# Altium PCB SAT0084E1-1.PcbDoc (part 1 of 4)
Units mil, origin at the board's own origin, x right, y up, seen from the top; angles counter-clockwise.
Board outline 7055 x 5555 mil, 6 copper layers (Top Layer, MidLayer1-GND, MidLayer2-HiSp, MidLayer3-GND, MidLayer4, Bottom Layer), stack 57.4 mil thick; 379 components, 207 nets, 1026 pads, 1546 vias.
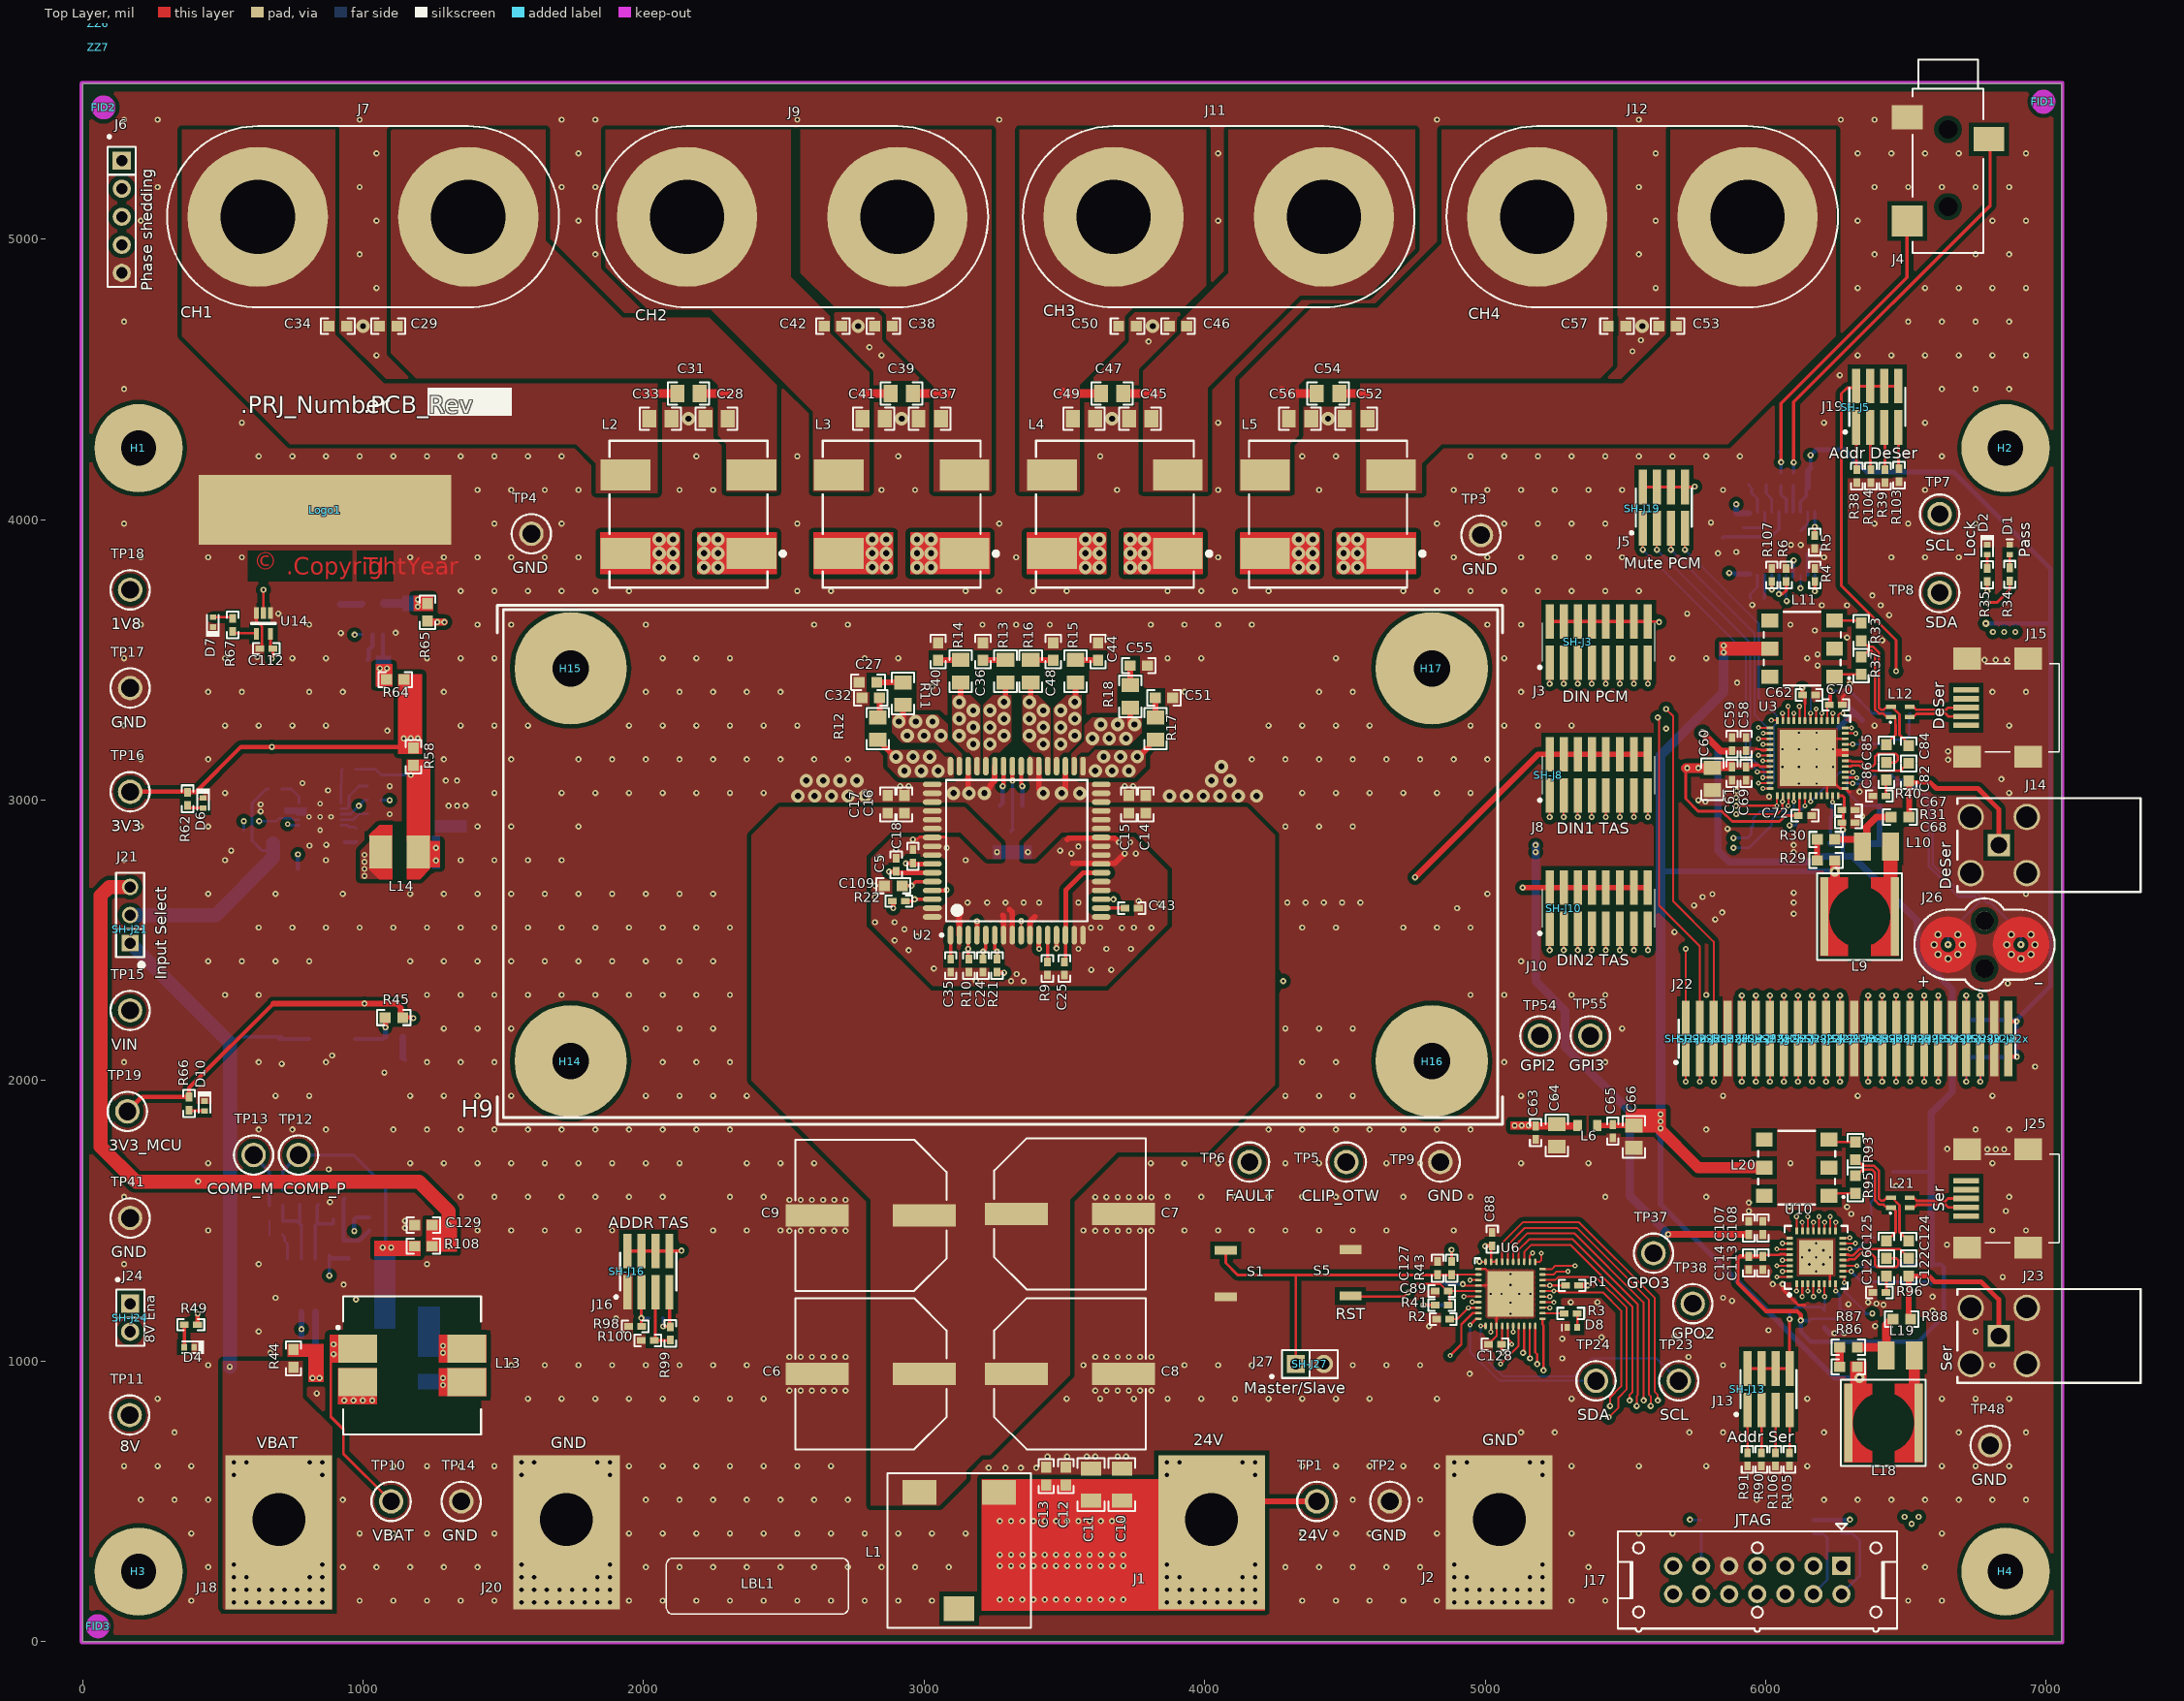
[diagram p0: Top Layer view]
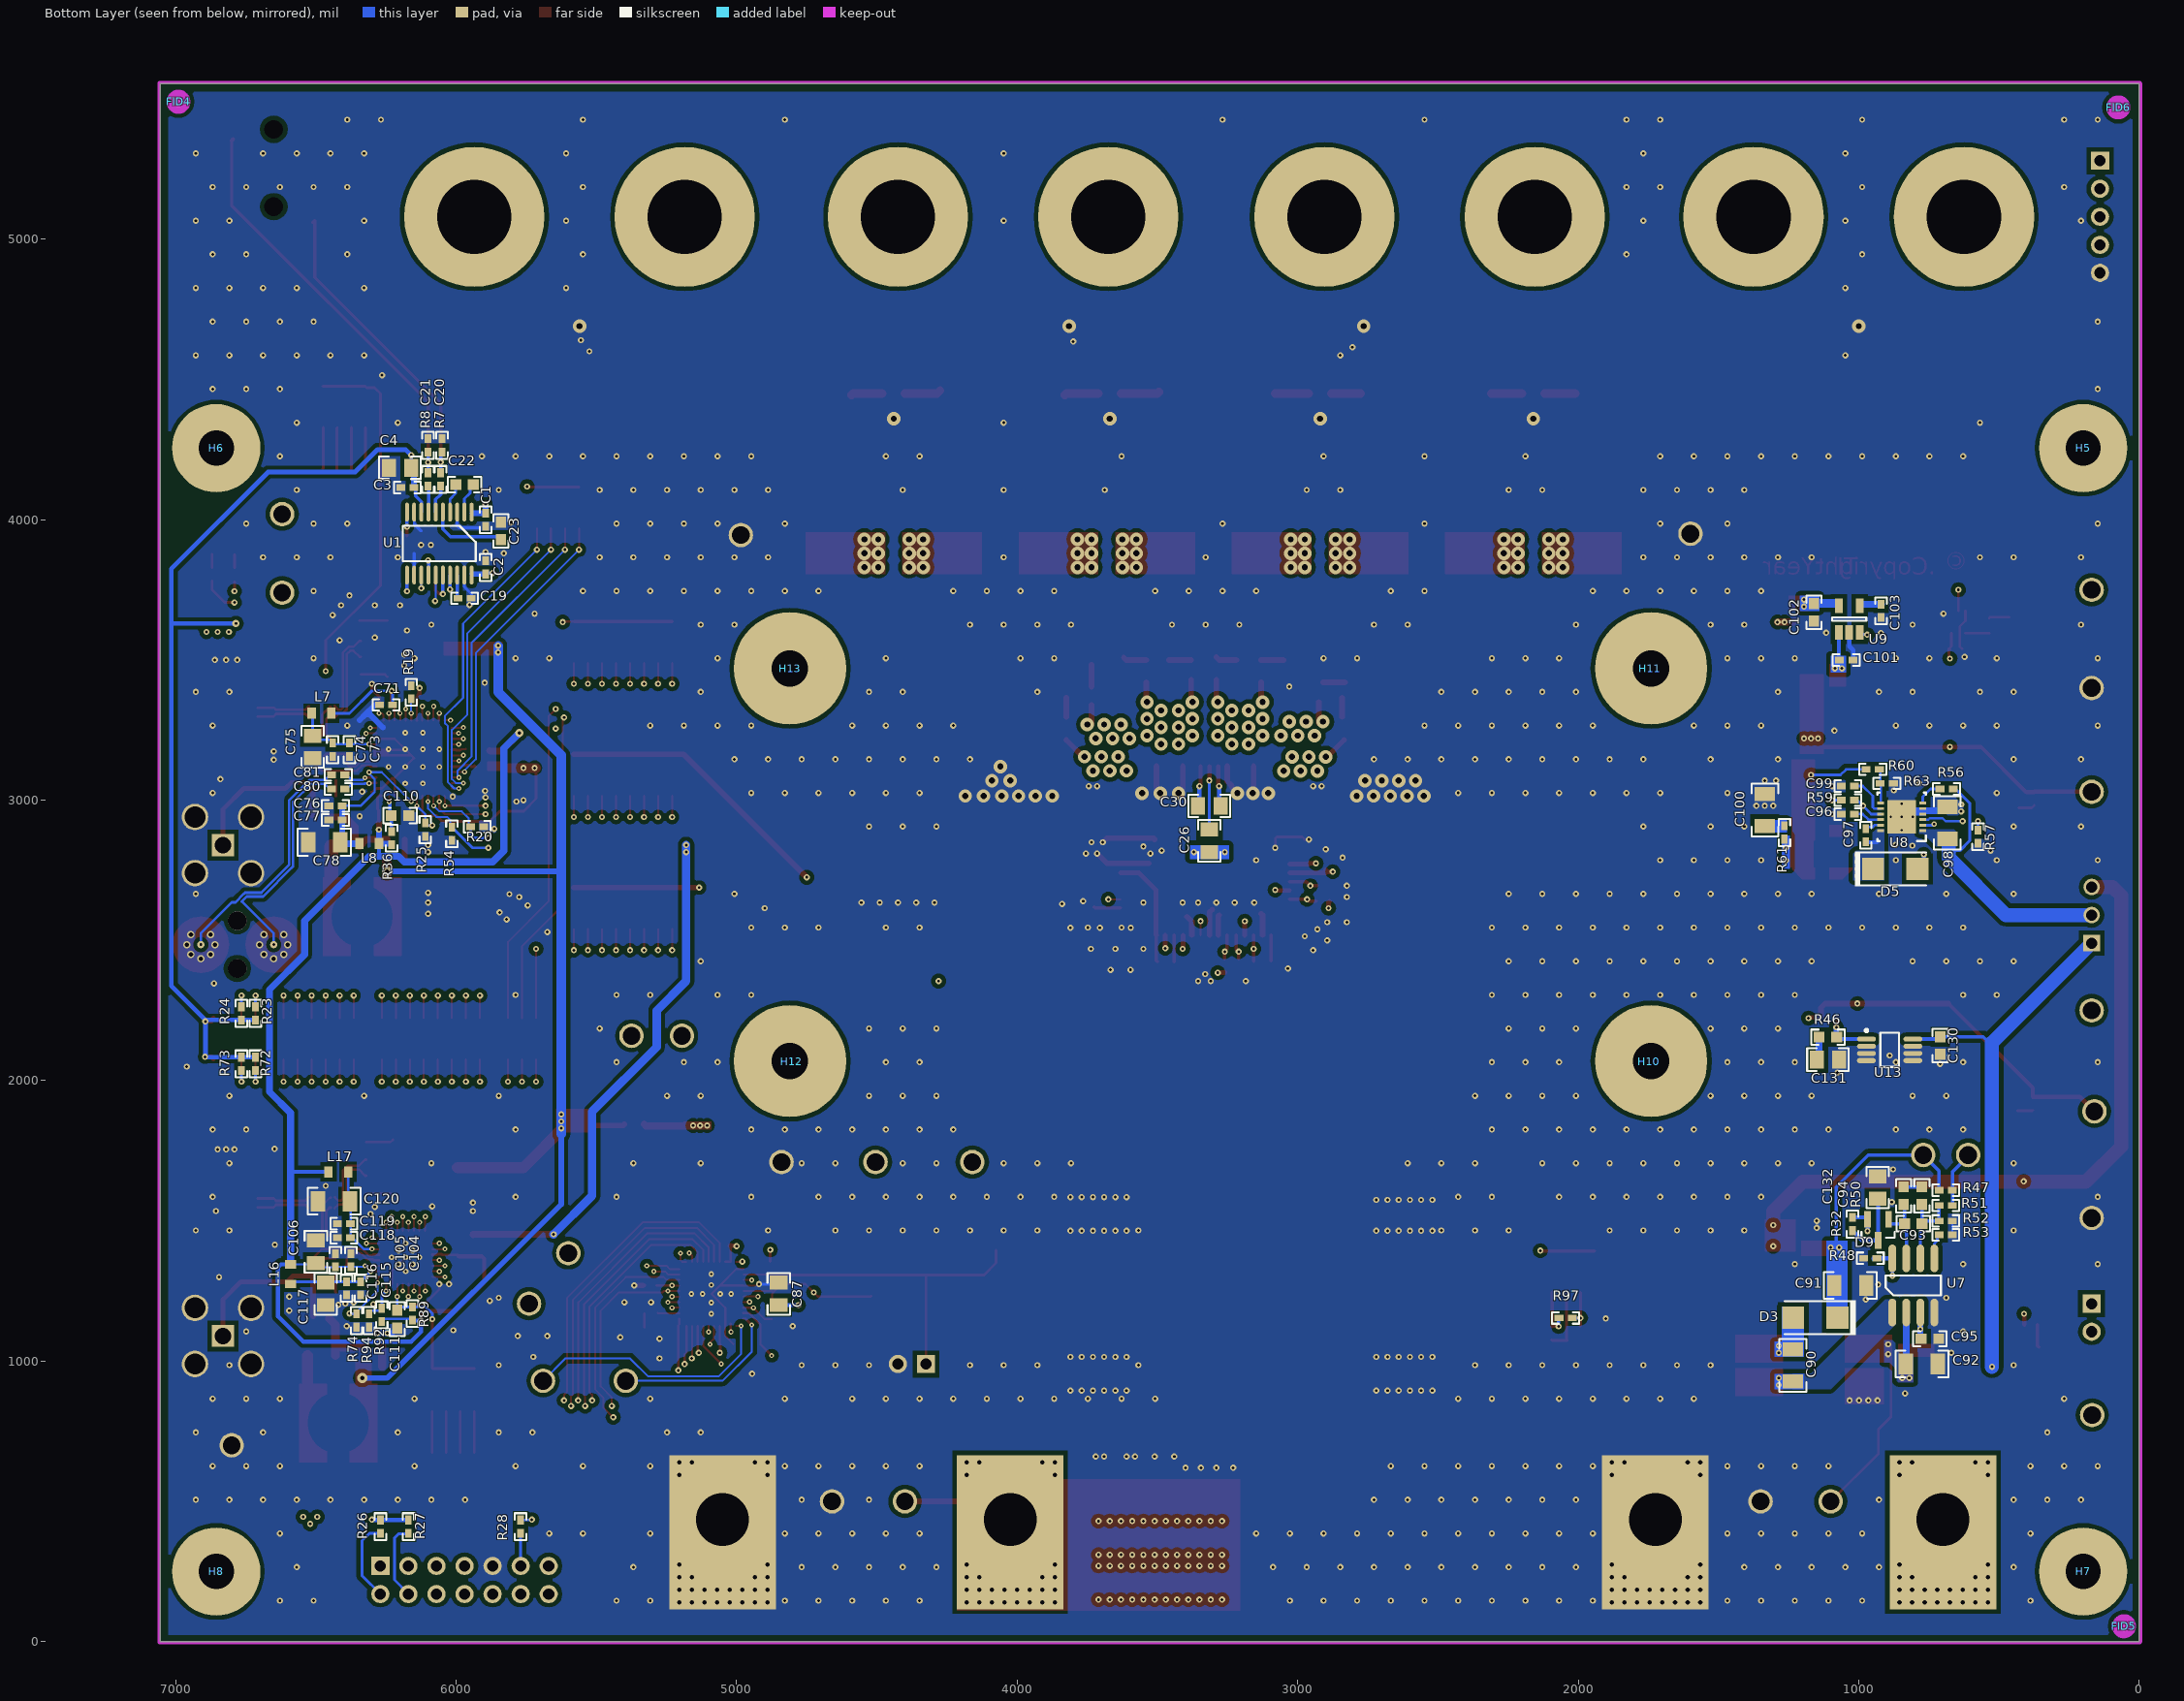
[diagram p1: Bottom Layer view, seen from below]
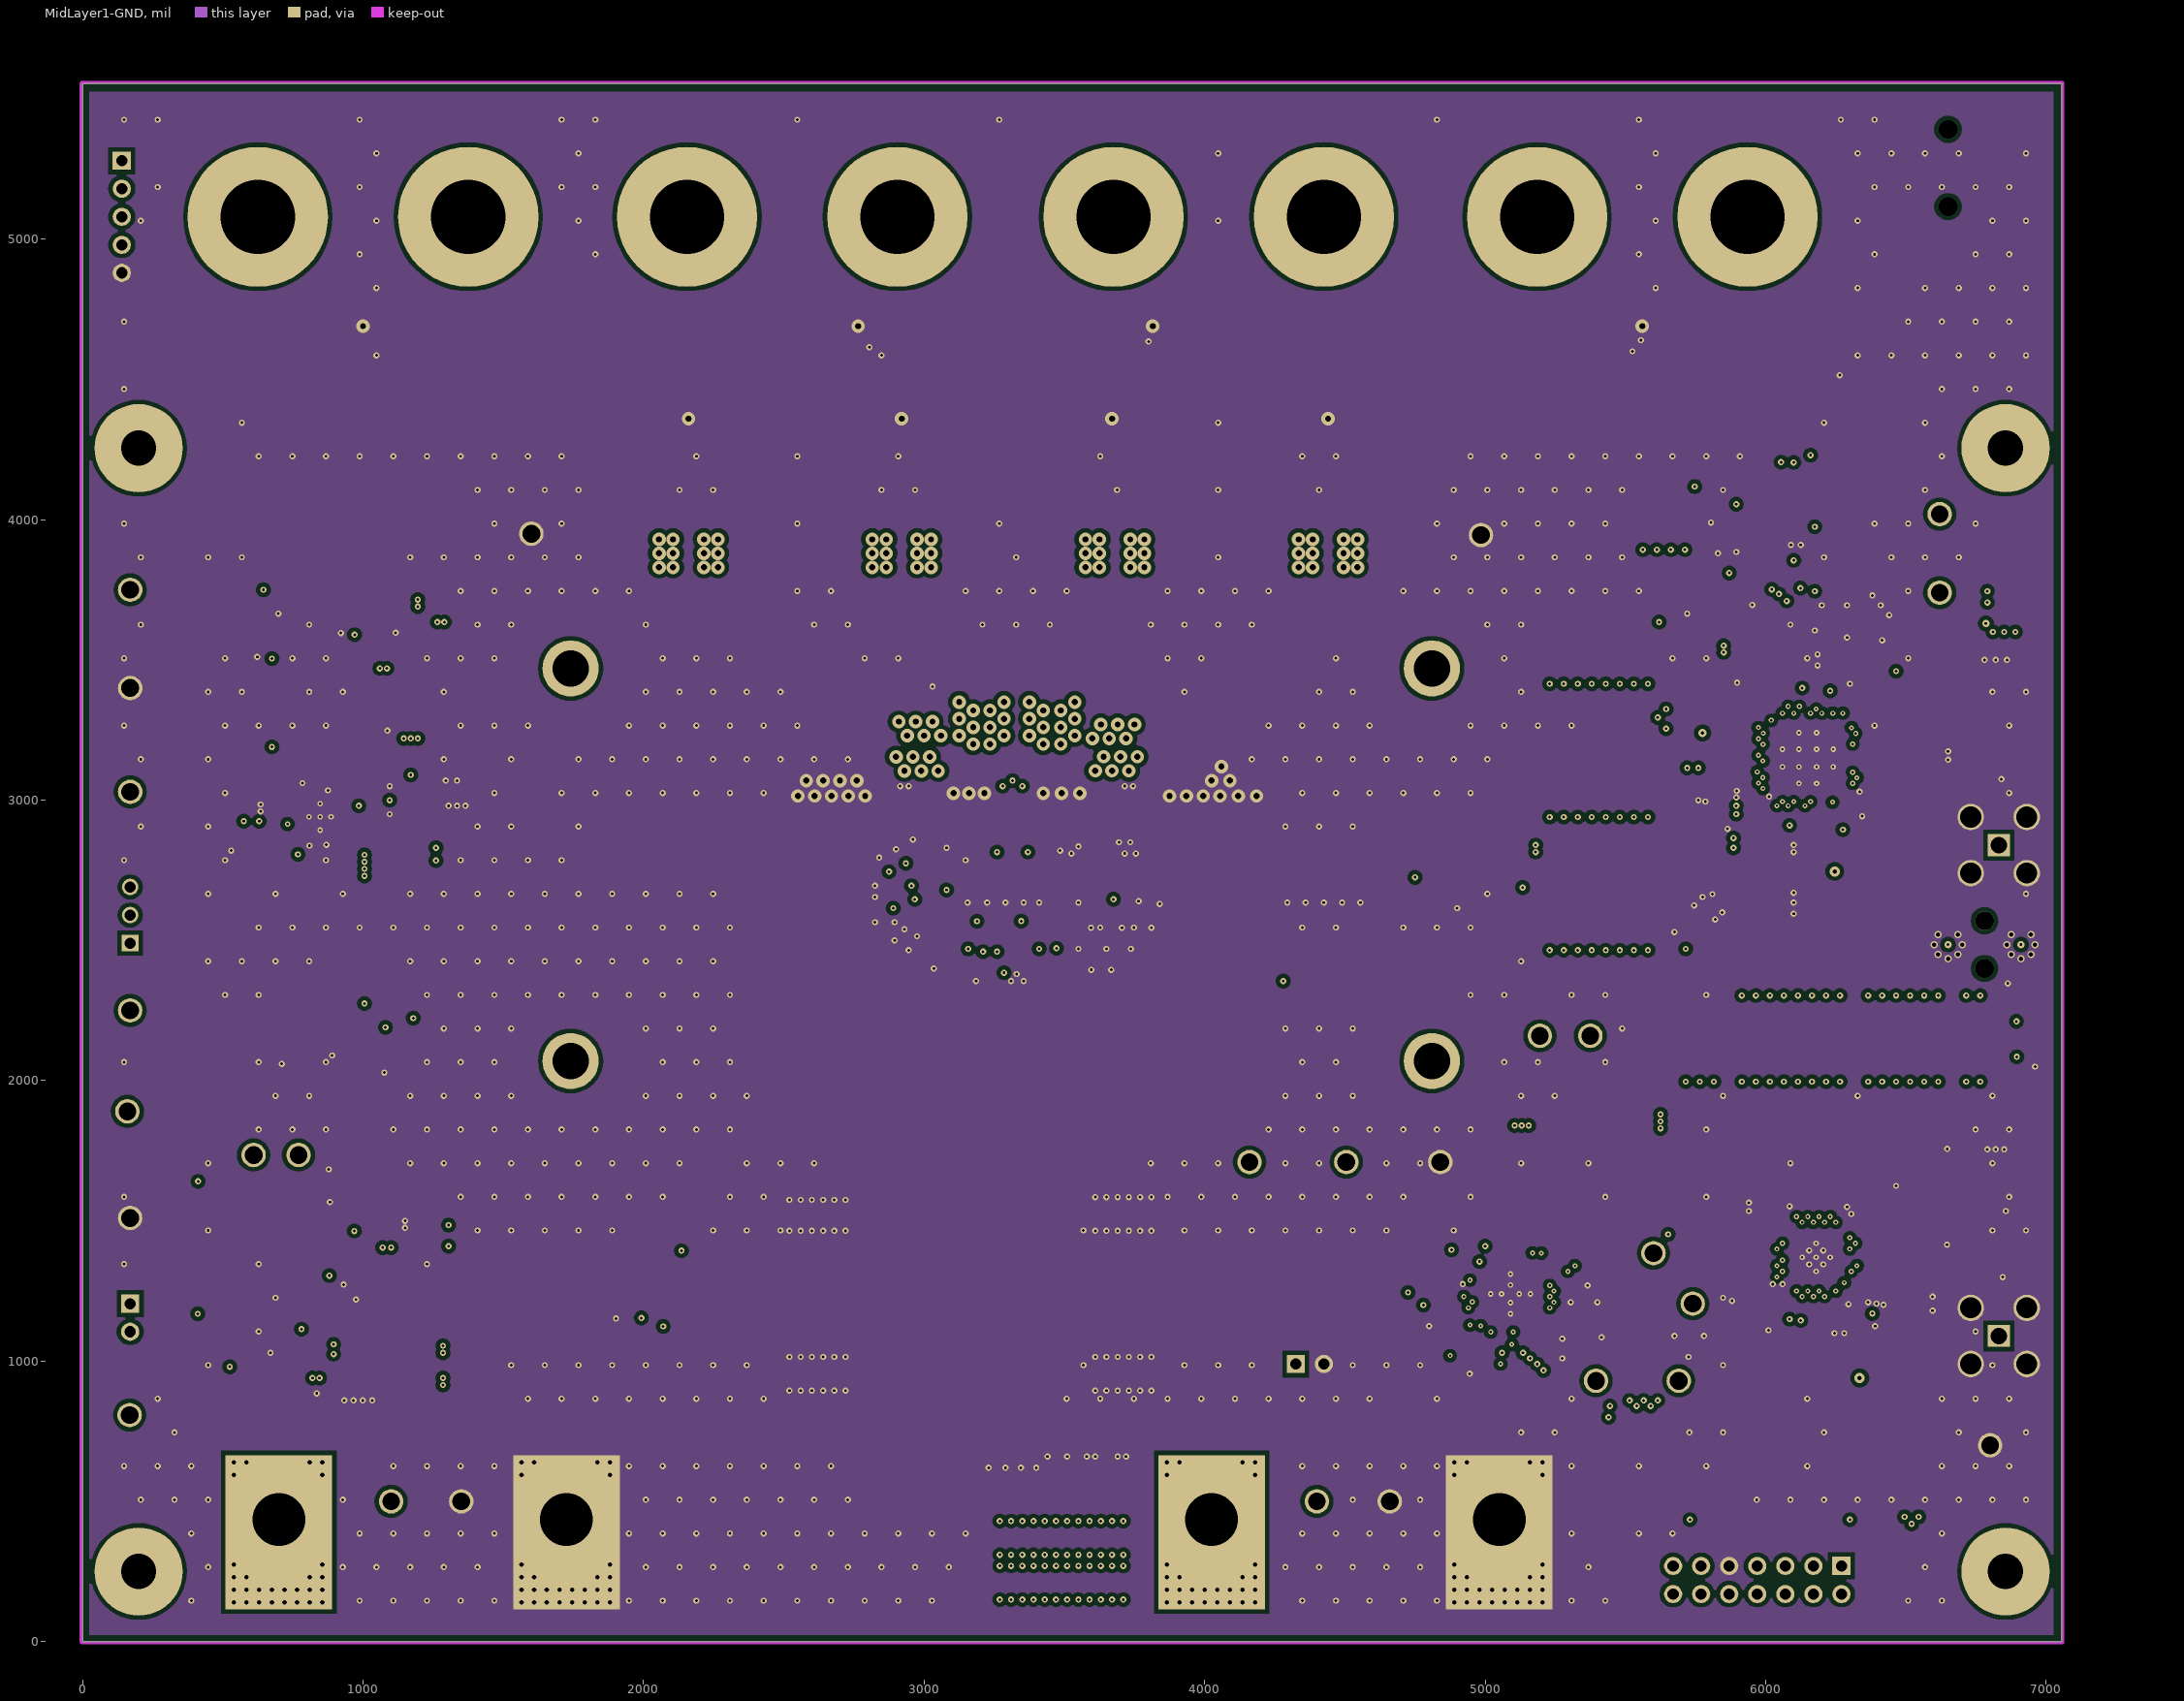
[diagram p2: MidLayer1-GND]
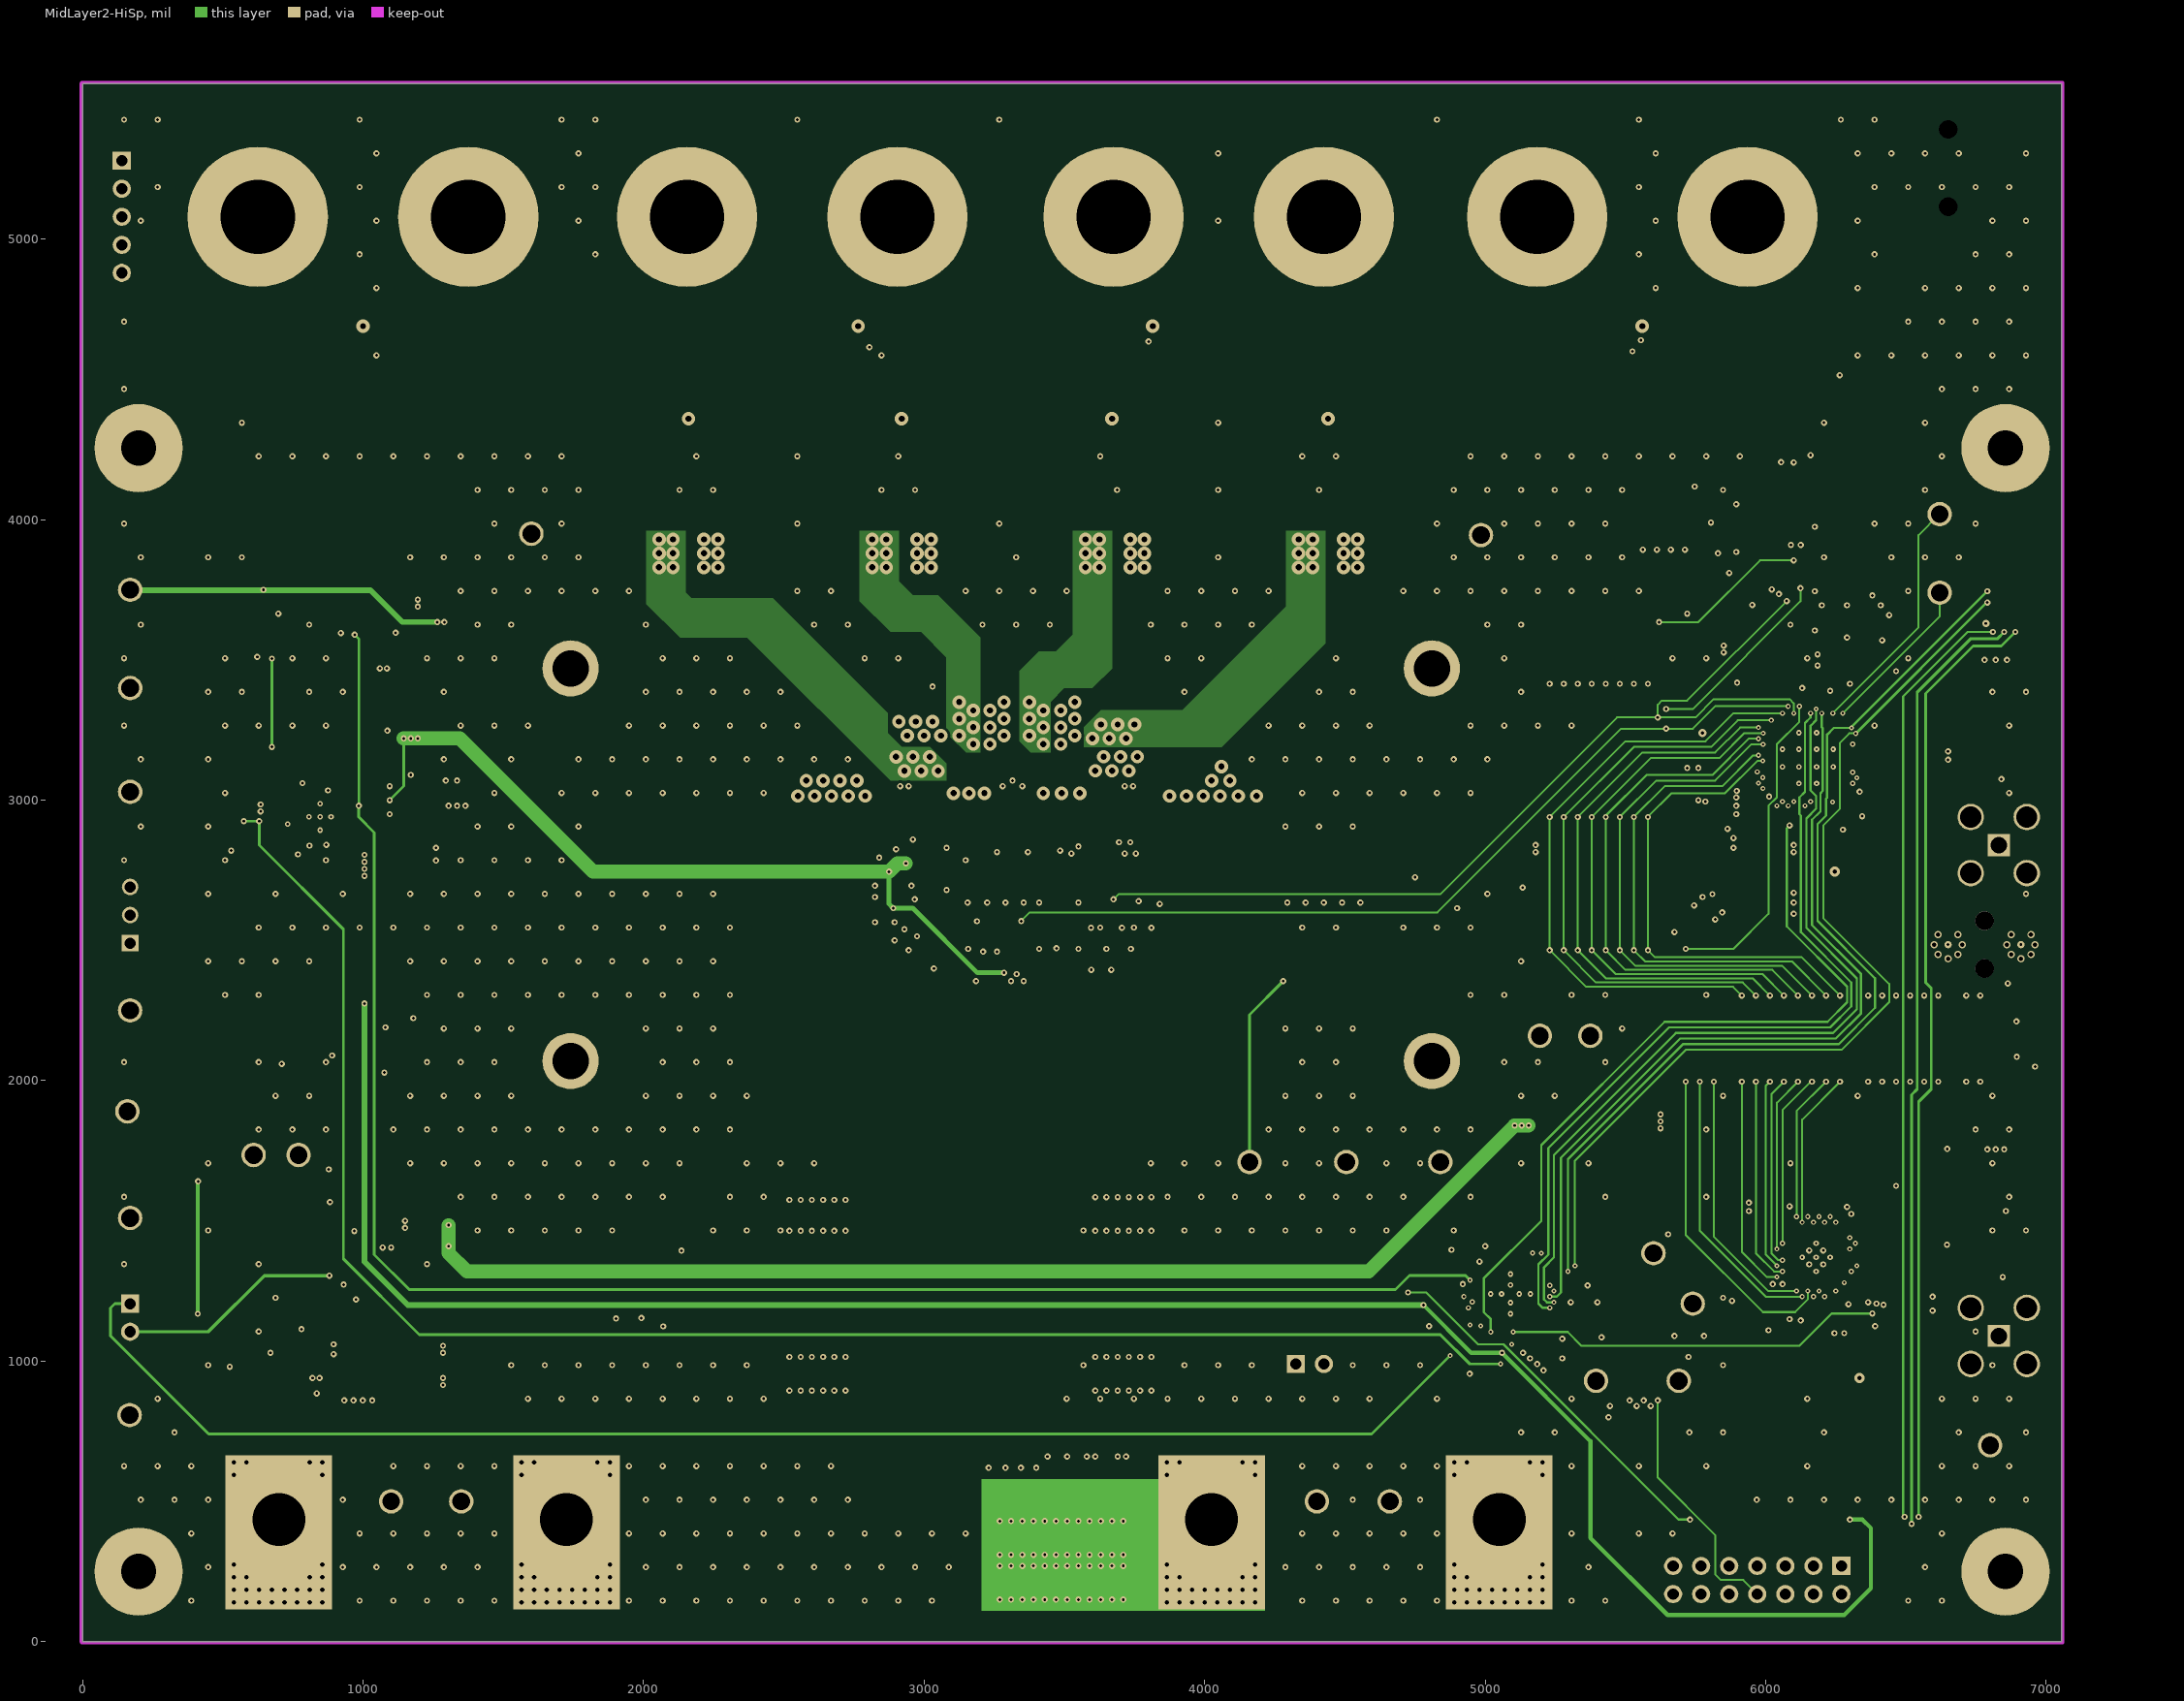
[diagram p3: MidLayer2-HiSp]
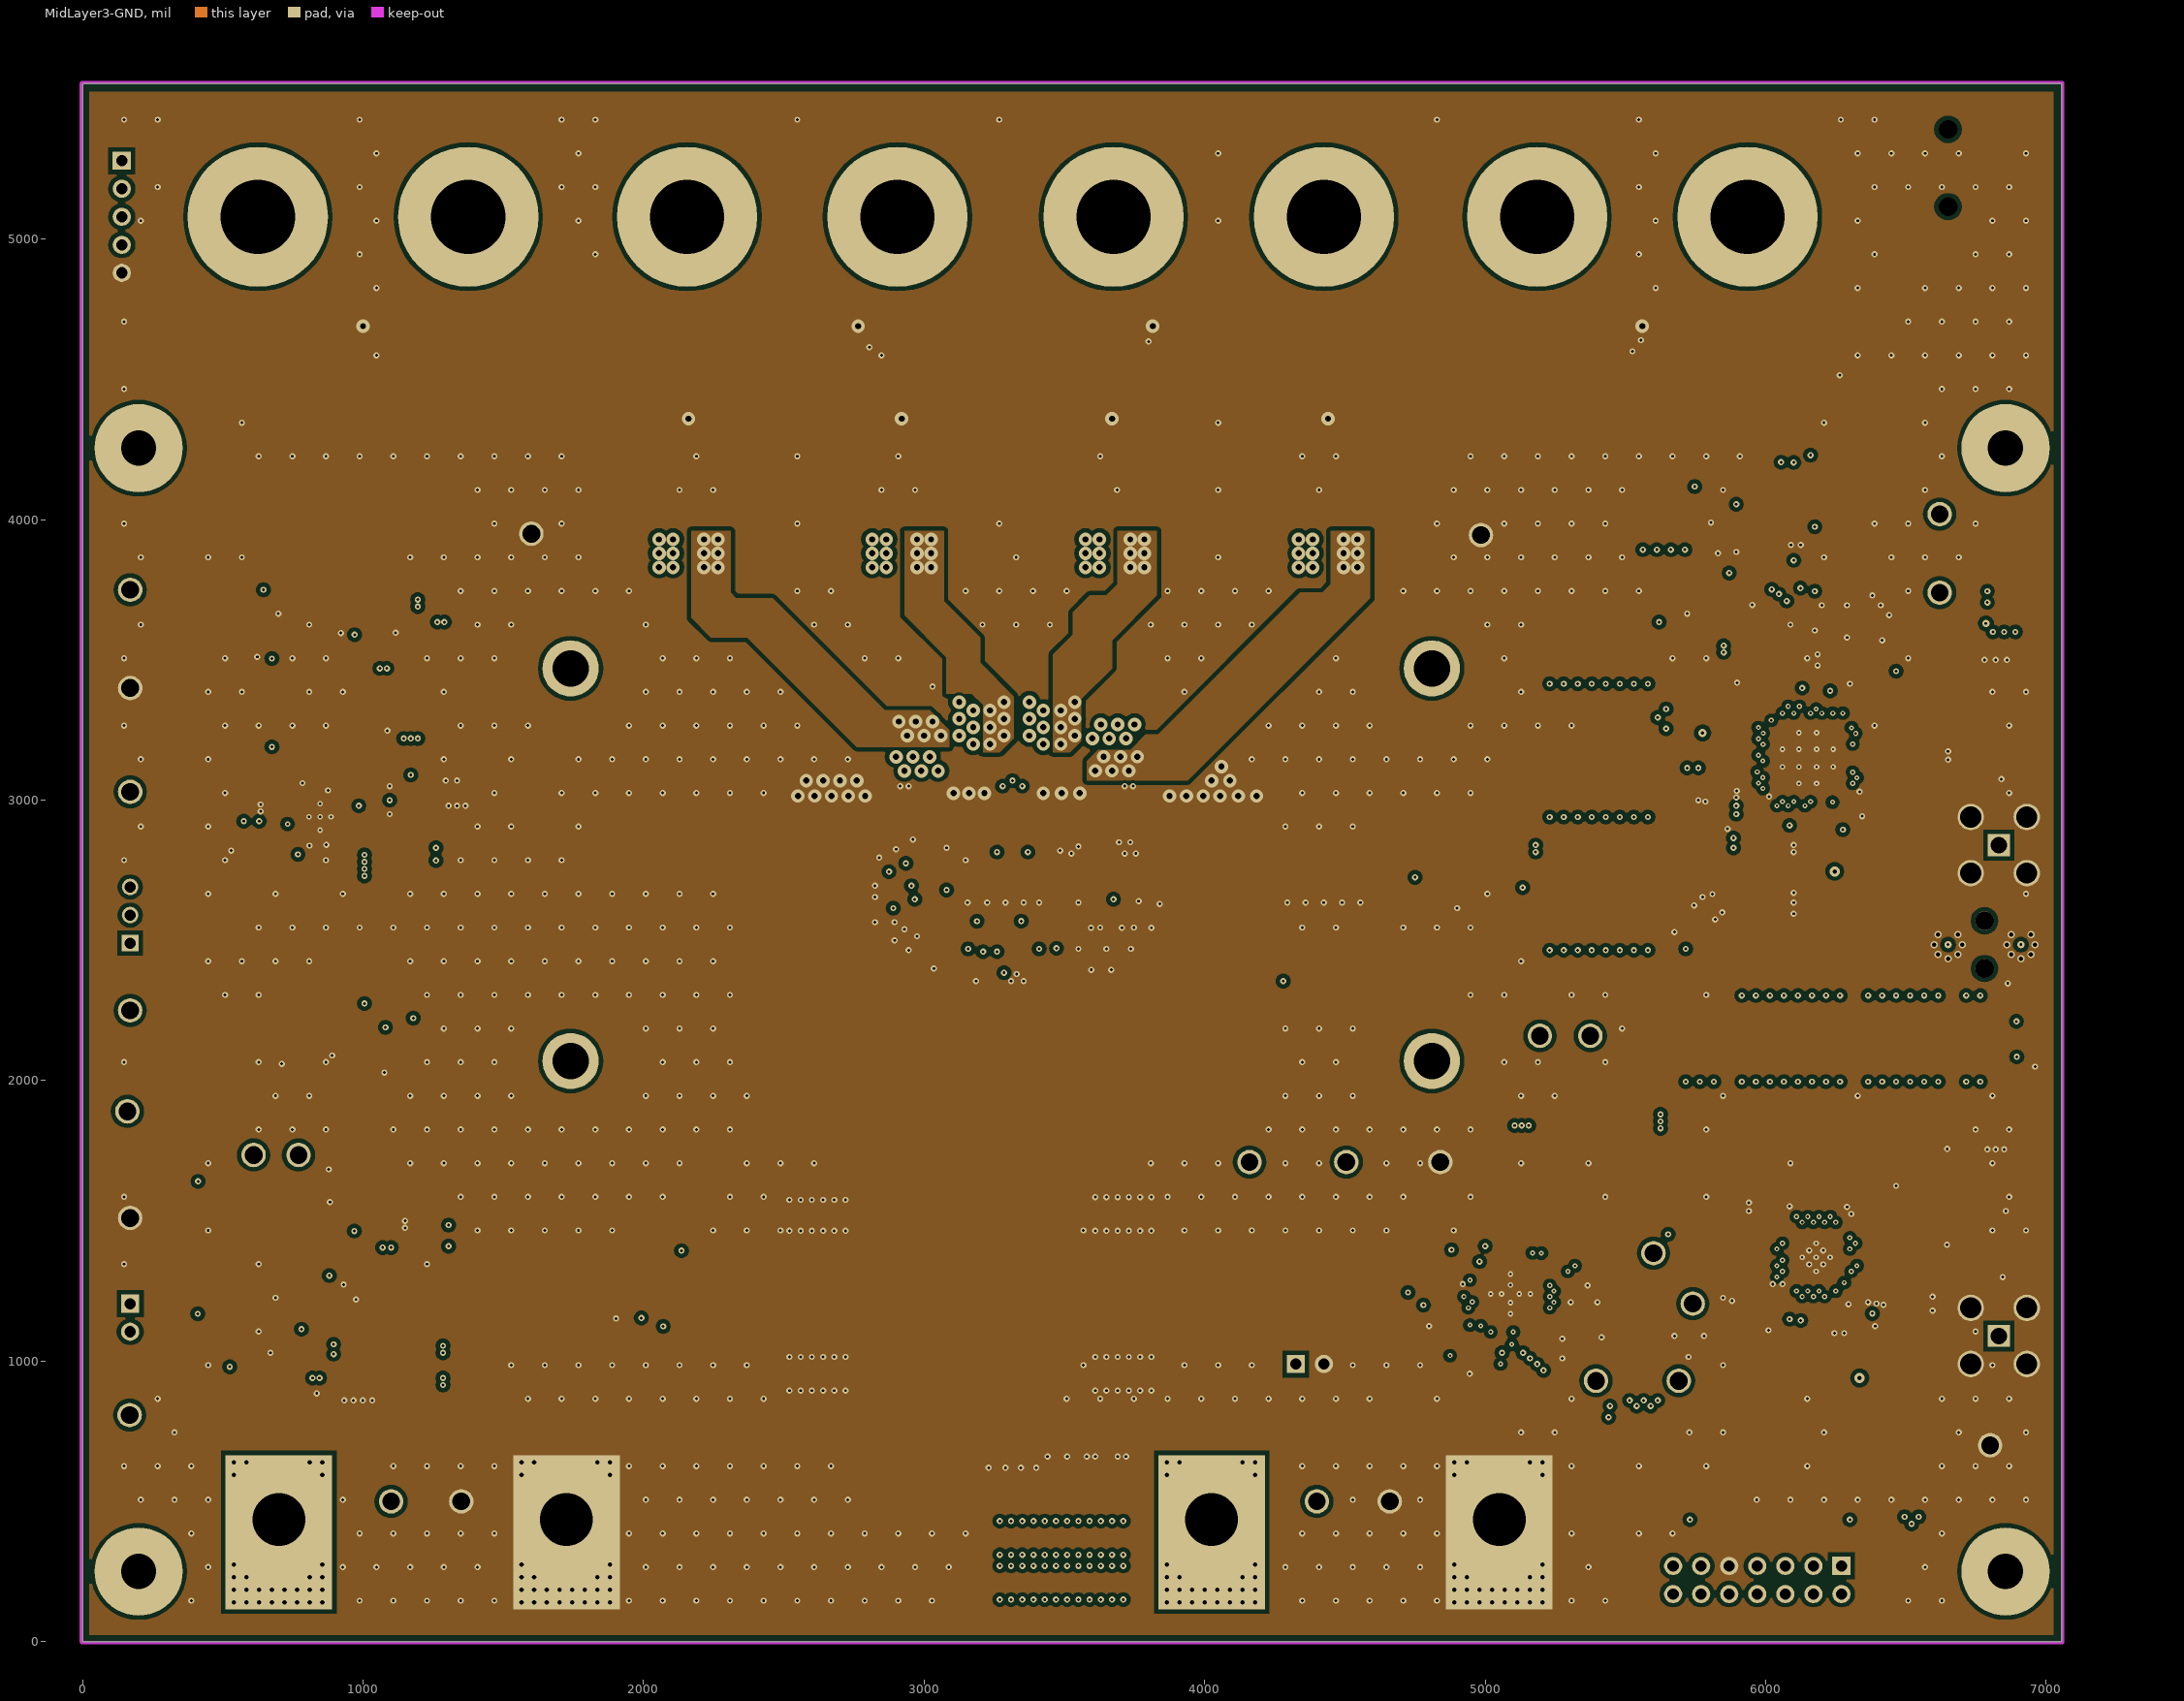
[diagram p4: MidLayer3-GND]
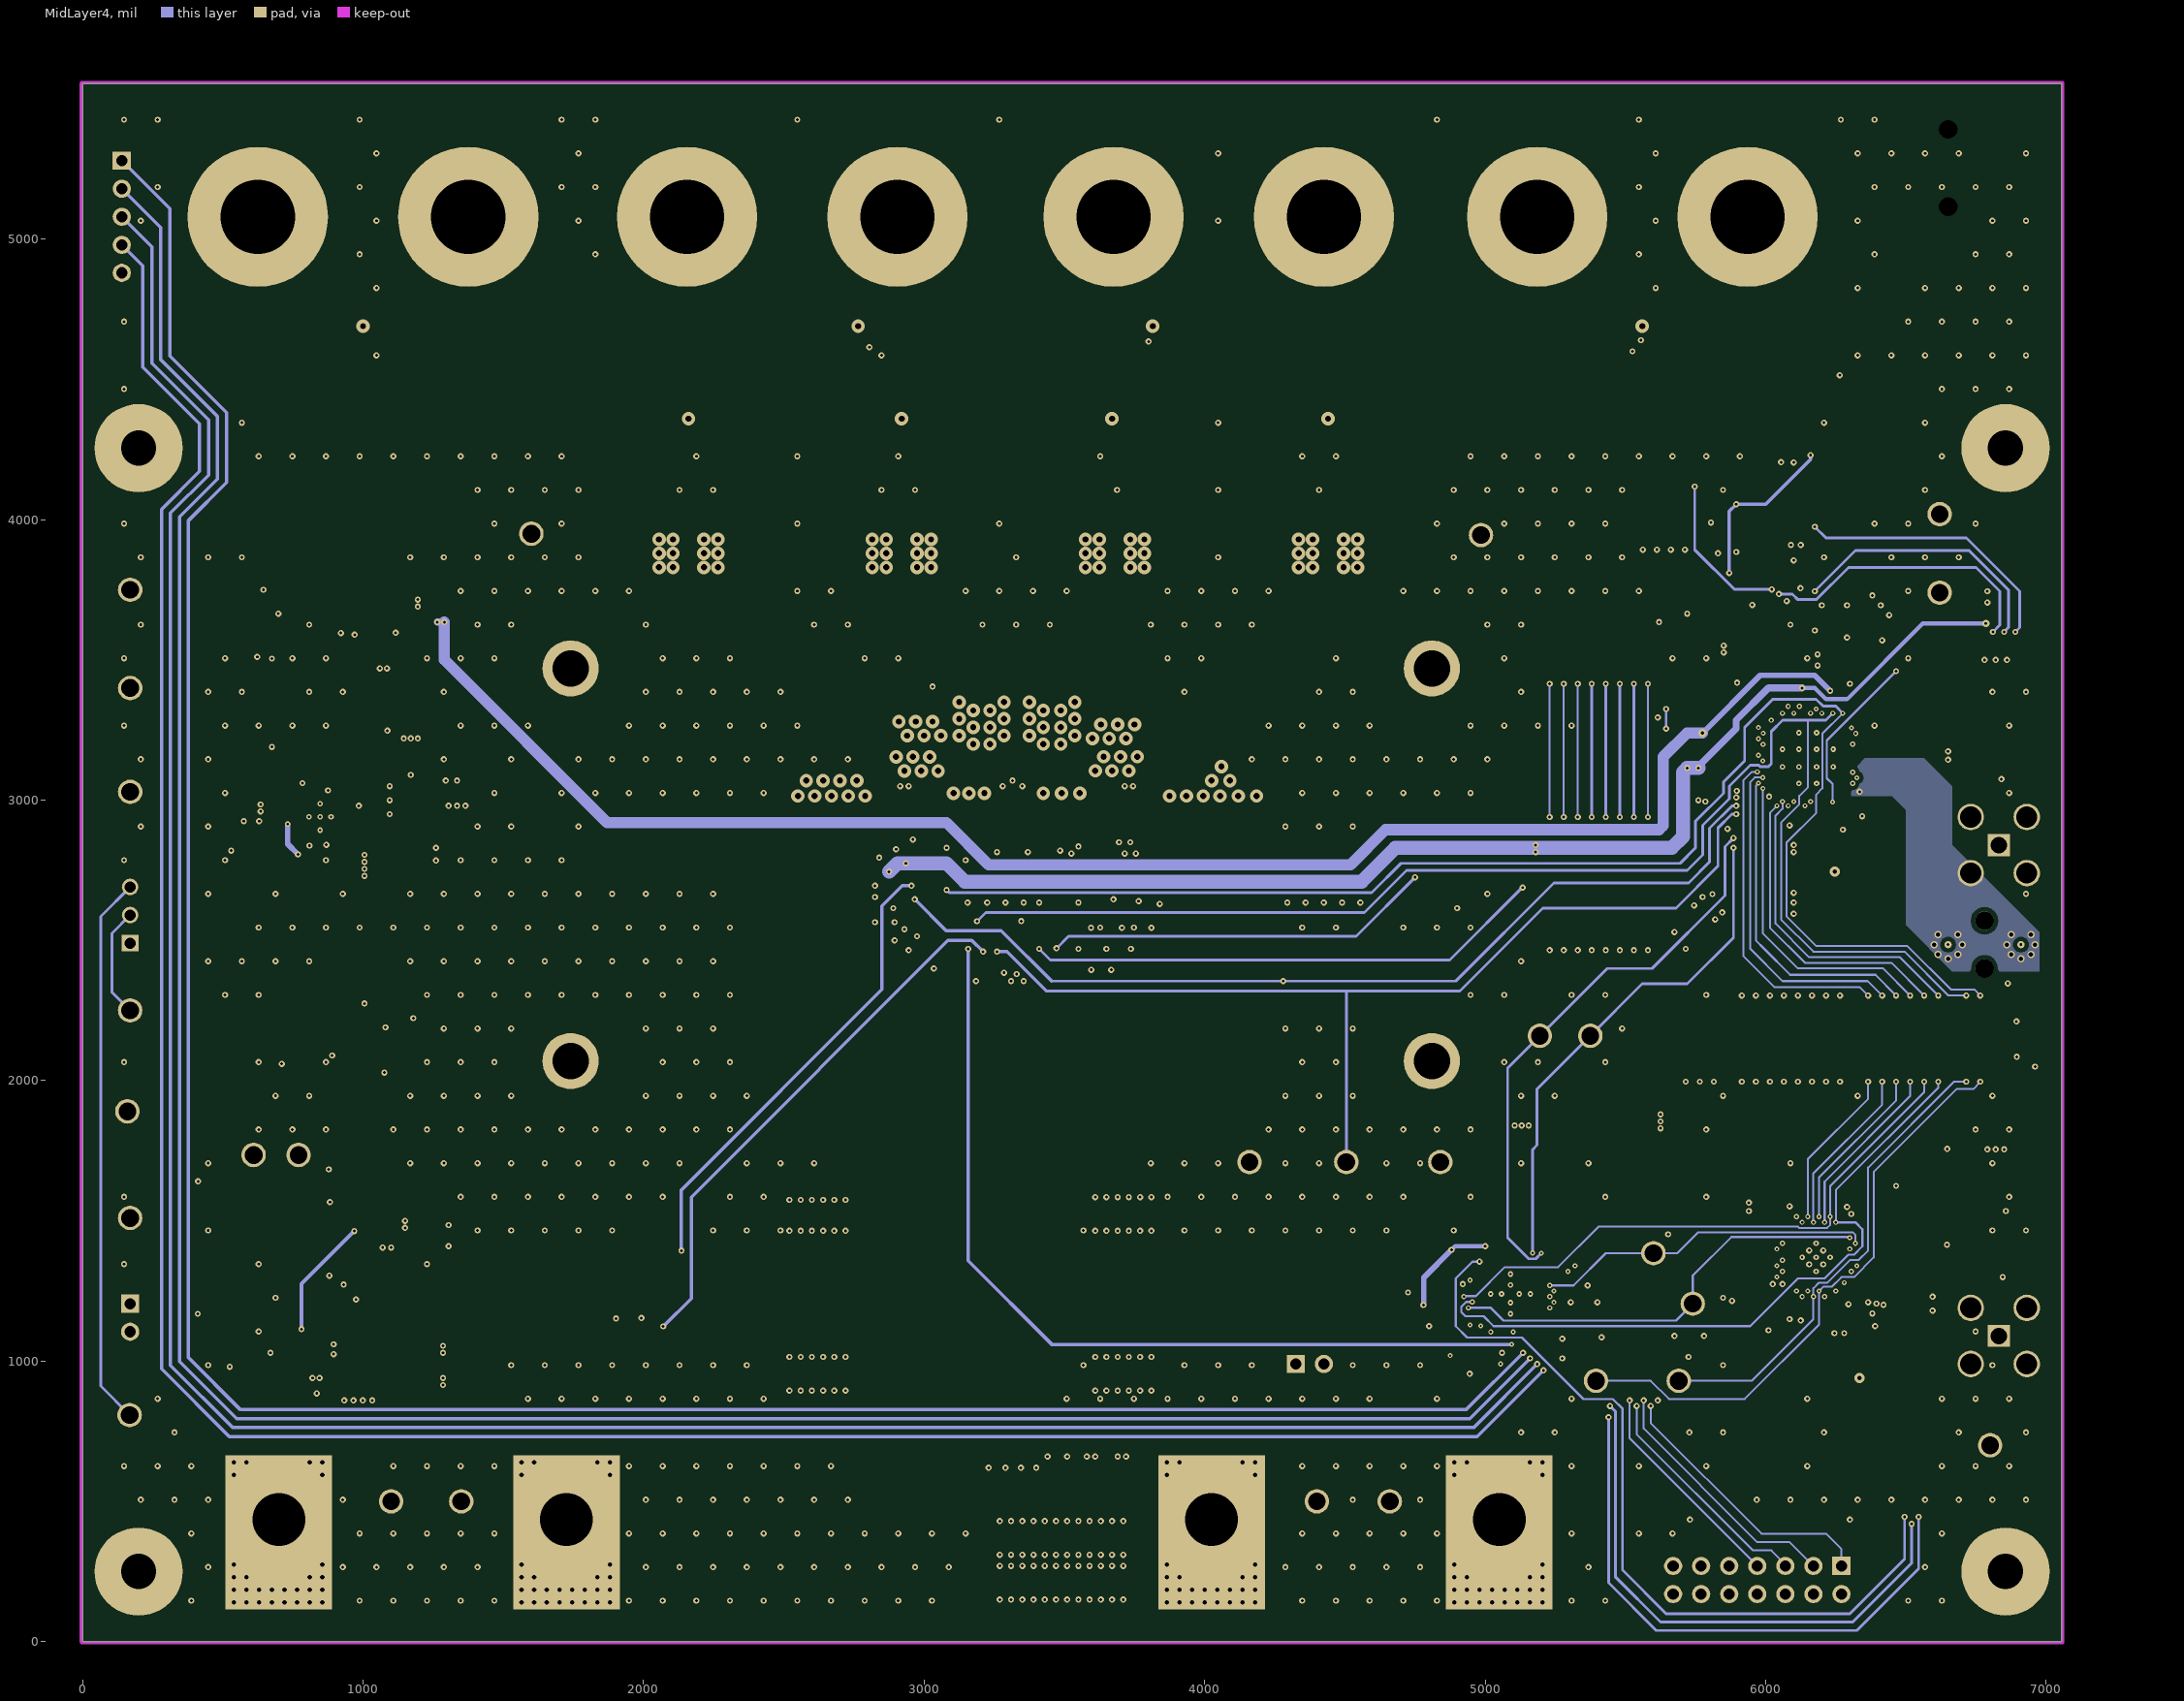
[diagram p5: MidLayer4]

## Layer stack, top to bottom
Top Layer: signal copper 1.4
Dielectric: core 9.8, FR-4 high TG, Dk 4.2
MidLayer1-GND: signal copper 1.4
Dielectric: prepreg 9.8, FR-4 high TG, Dk 4.2
MidLayer2-HiSp: signal copper 1.4
Dielectric: core 9.8, FR-4 high TG, Dk 4.2
MidLayer3-GND: signal copper 1.4
Dielectric: prepreg 9.8, FR-4 high TG, Dk 4.2
MidLayer4: signal copper 1.4
Dielectric: core 9.8, FR-4 high TG, Dk 4.2
Bottom Layer: signal copper 1.4

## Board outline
0,0 0,5555 7055,5555 7055,0

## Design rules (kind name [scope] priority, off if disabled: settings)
AcuteAngle [All] p1: minimum=4.50000000000000E+0001 checktracksonly=FALSE
AssemblyTestPointUsage [All] p1: valid=2
Clearance "Clearance D7" [InComponent('D7')] p1: gap=6
Clearance Clearance_Poly_GND [Inpoly and InNet(GND)] p2: gap=15
Clearance Clearance_Poly [InPolygon] p3: gap=10
Clearance "Clearance_diffpair 100ohm outer" [InDifferentialPair('CMLOUT') or InDifferentialPair('CMLOUTC') or InDifferentialPair('FPD_DIN') or InDifferentialPair('DIN')  or InDifferentialPair('DESER_DIN') or InDifferentialPair('FPD_DOUT') or InDifferentialPair('DOUT') or InDifferentialPair('SER_DOUT')] p4: gap=5
Clearance Clearance_BoardEdge_Poly [OnCopper and InPoly vs IsKeepOut] p5: gap=25
Clearance Clearance_BoardEdge [OnCopper and Not InComponentClass('Logo') and not InComponentClass('FiducialMark') and not InRegion(1000,500,4000,800) and Not IsKeepout vs IsKeepOut] p6: gap=25
Clearance Clearance_BoardEdge_MountingHoles [OnCopper and InComponentClass('Mounting Holes') vs IsKeepOut] p7: gap=40
Clearance Clearance_1 [All] p8: gap=7
ComponentClearance ComponentClearance_Shunt [InComponentClass('Header') vs InComponentClass('Shunt')] p1 off: gap=0 collisioncheckmode=3 verticalgap=0 showdistances=FALSE
ComponentClearance ComponentClearance_Logo [InComponentClass('Logo')] p2 off: gap=50 collisioncheckmode=3 verticalgap=10 showdistances=FALSE
ComponentClearance ComponentClearance_ScrewToNut [(HasFootprint('NY PMS 440 0025 PH')) vs (HasFootprint('Keystone_1902C'))] p3 off: gap=5 collisioncheckmode=3 verticalgap=10 showdistances=FALSE
ComponentClearance ComponentClearance_MountingHoles [InComponentClass('Mounting Holes')] p4 off: gap=250 collisioncheckmode=3 verticalgap=100000 showdistances=FALSE
ComponentClearance ComponentClearance_SmallPassives [HasFootprint('0201*') or HasFootprint('0402*') or HasFootprint('0508') or HasFootprint('0603*') or HasFootprint('0612') or HasFootprint('0805*') or HasFootprint('0815*') or HasFootprint('0830*') or HasFootprint('1206*') or HasFootprint('1210*') or HasFootprint('1808*') or HasFootprint('1812*') or HasFootprint('1825*') or HasFootprint('2010*') or HasFootprint('2220*') or HasFootprint('2225*') or HasFootprint('2512*') or HasFootprint('2728*') or HasFootprint('3518*') vs HasFootprint('0201*') or HasFootprint('0402*') or HasFootprint('0508') or HasFootprint('0603*') or HasFootprint('0612') or HasFootprint('0805*') or HasFootprint('0815*') or HasFootprint('0830*') or HasFootprint('1206*') or HasFootprint('1210*') or HasFootprint('1808*') or HasFootprint('1812*') or HasFootprint('1825*') or HasFootprint('2010*') or HasFootprint('2220*') or HasFootprint('2225*') or HasFootprint('2512*') or HasFootprint('2728*') or HasFootprint('3518*')] p5 off: gap=20 collisioncheckmode=3 verticalgap=10 showdistances=FALSE
ComponentClearance ComponentClearance_THtoSMT [IsThruComponent vs IsSMTComponent] p6 off: gap=100 collisioncheckmode=3 verticalgap=30 showdistances=FALSE
ComponentClearance ComponentClearance_THtoTH [IsThruComponent vs IsThruComponent] p7 off: gap=118.11 collisioncheckmode=3 verticalgap=30 showdistances=FALSE
ComponentClearance [All] p8 off: gap=40 collisioncheckmode=3 verticalgap=10 showdistances=FALSE
DiffPairsRouting "DiffPairsRouting outer 100 ohm" [All] p1: maxlimit=400 minlimit=5 mostfreqgap=5 toplayer_maxgap=200 midlayer1_maxgap=100 midlayer2_maxgap=100 midlayer3_maxgap=100 midlayer4_maxgap=100 maxuncoupledlength=1000
FabricationTestPointUsage TestPointUsage [All] p1: valid=2 allowmultiple=FALSE
FabricationTestpoint Testpoint [All] p1: side=3 testpointundercomponent=TRUE minsize=40 maxsize=100 preferedsize=60 minholesize=0 maxholesize=40 preferedholesize=32 testpointgrid=1 allowsidetop=TRUE allowsidebottom=TRUE usegrid=TRUE gridtolerance=0.01
FanoutControl Fanout_LCC [IsLCC] p1: bgadir=Out bgaviamode=Centered fanoutstyle=Auto fanoutdirection=Alternating viagrid=1 // Fanout_LCC (Default Rule)
FanoutControl Fanout_BGA [IsBGA] p2: bgadir=Out bgaviamode=Centered fanoutstyle=Auto fanoutdirection=Alternating viagrid=1 // Fanout_BGA (Default Rule)
FanoutControl Fanout_Default [All] p4: bgadir=Out bgaviamode=Centered fanoutstyle=Auto fanoutdirection=Alternating viagrid=1 // Fanout_Default (Default Rule)
FanoutControl Fanout_Small [(CompPinCount < 5)] p5: bgadir=Out bgaviamode=Centered fanoutstyle=Auto fanoutdirection=OutThenIn viagrid=1 // Fanout_Small (Default Rule)
Height [All] p1 off: minheight=0 maxheight=1000 prefheight=500
HoleSize [All] p1: absolutevalues=TRUE maxlimit=300 minlimit=7.8 maxpercent=80.000 minpercent=20.000
Length Length_SER [InNetClass('Ser_I2S')] p1 off: maxlimit=1255 minlimit=1200
Length [InNetClass(I2S_D)] p2 off: maxlimit=2850 minlimit=2800
MinimumAnnularRing MinimumAnnularRing_ThermalPadVias [IsVia and InAnyComponent] p1 off: minimumring=5.91
MinimumAnnularRing [All] p2: minimumring=5
MinimumSolderMaskSliver MinimumSolderMaskSliver_Logo [InComponentClass('Logo') vs InComponentClass('Logo')] p1: minsoldermaskwidth=0.7
MinimumSolderMaskSliver [All] p2: minsoldermaskwidth=3.94
PlaneConnect [All] p1: planeconnectstyle=Relief reliefexpansion=10 reliefentries=4 reliefconductorwidth=10 reliefairgap=10
PolygonConnect [All] p1: connectstyle=Direct reliefconductorwidth=10 reliefentries=4 polygonreliefangle="90 Angle" airgapwidth=10
RoutingVias ThermalPadVias [IsVia and InAnyComponent] p1 off: holewidth=7.87 width=19.68 viastyle="Through Hole" minholewidth=7.87 minwidth=19.68 maxholewidth=12.99 maxwidth=23.62
RoutingVias [All] p2: holewidth=10 width=22 viastyle="Through Hole" minholewidth=7.87 minwidth=18 maxholewidth=40 maxwidth=65
SMDToCorner [All] p1: distance=28000
SilkToSilkClearance [All] p1 off: silktosilkclearance=2
SilkscreenOverComponentPads [All] p1: minsilkscreentomaskgap=2
SolderMaskExpansion [All] p1: expansion=1
Width "Width_diffpair outer 100ohm" [InDifferentialPair('CMLOUT') or InDifferentialPair('CMLOUTC')  or InDifferentialPair('FPD_DIN') or InDifferentialPair('DIN')  or InDifferentialPair('DESER_DIN')  or InDifferentialPair('FPD_DOUT') or InDifferentialPair('DOUT') or InDifferentialPair('SER_DOUT')] p1: maxlimit=9 minlimit=9 preferedwidth=9 minimp=50.000000 maximp=50.000000 favimp=50.000000
Width [All] p2: maxlimit=100 minlimit=6 preferedwidth=10 checkconnectedcopper=TRUE
13 further rules are at their usual default settings.

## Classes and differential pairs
component class SAT0084E1-1_Ser: C104 C105 C106 C107 C108 C111 C113 C114 C115 C116 C117 C118 C119 C120 C122 C124 C125 C126 J13 J22 J23 J25 L16 L17 L18 L19 L20 L21 R1 R2 R72 R73 R74 R86 R87 R88 R89 R90 R91 R92 R93 R94 R95 R96 R105 R106 TP23 TP24 TP37 TP38 TP48 U10
component class SAT0084E1-1_Power: C90 C91 C92 C93 C94 C95 C96 C97 C98 C99 C100 C101 C102 C103 C112 C129 C130 C131 C132 D3 D4 D5 D6 D7 D9 D10 J18 J20 J21 J24 L13 L14 R32 R44 R45 R46 R47 R48 R49 R50 R51 R52 R53 R56 R57 R58 R59 R60 R61 R62 R63 R64 R65 R66 R67 R108 TP10 TP11 TP12 TP13 TP14 TP15 TP16 TP17 TP18 TP19 TP41 U7 U8 U9 U13 U14
component class SAT0084E1-1_MCU: C87 C88 C89 C127 C128 D8 J6 J17 J27 R3 R26 R27 R28 R41 R43 S1 S5 U6
component class SAT0084E1-1_DeSer: C58 C59 C60 C61 C62 C63 C64 C65 C66 C67 C68 C69 C70 C71 C72 C73 C74 C75 C76 C77 C78 C80 C81 C82 C84 C85 C86 C110 D1 D2 J14 J15 J19 J26 L6 L7 L8 L9 L10 L11 L12 R19 R20 R23 R24 R25 R29 R30 R31 R33 R34 R35 R36 R37 R38 R39 R40 R54 R103 R104 TP7 TP8 TP9 TP54 TP55 U3
component class SAT0084E1-1_Backend: C1 C2 C3 C4 C5 C6 C7 C8 C9 C10 C11 C12 C13 C14 C15 C16 C17 C18 C19 C20 C21 C22 C23 C24 C25 C26 C27 C28 C29 C30 C31 C32 C33 C34 C35 C36 C37 C38 C39 C40 C41 C42 C43 C44 C45 C46 C47 C48 C49 C50 C51 C52 C53 C54 C55 C56 C57 C109 J1 J2 J3 J4 J5 J7 J8 J9 J10 J11 J12 J16 L1 L2 L3 L4 L5 R4 R5 R6 R7 R8 R9 R10 R11 R12 R13 R14 R15 R16 R17 R18 R21 R22 R97 R98 R99 R100 R107 TP1 TP2 TP3 TP4 TP5 TP6 U1 U2
component class Label: LBL1
component class AssemblyNote: ZZ1 ZZ2 ZZ3 ZZ4 ZZ5 ZZ6 ZZ7
component class FiducialMark: FID1 FID2 FID3 FID4 FID5 FID6
component class SAT0084E1-1_Hardware: FID1 FID2 FID3 FID4 FID5 FID6 H1 H2 H3 H4 H5 H6 H7 H8 H9 H10 H11 H12 H13 H14 H15 H16 H17 LBL1 Logo1 SH-J3 SH-J5 SH-J8 SH-J10 SH-J13 SH-J16 SH-J19 SH-J21 SH-J22a SH-J22b SH-J22c SH-J22d SH-J22e SH-J22f SH-J22g SH-J22h SH-J22i SH-J22j SH-J22k SH-J22l SH-J22m SH-J22n SH-J22o SH-J22p SH-J22q SH-J22r SH-J22s SH-J22t SH-J22u SH-J22v SH-J22w SH-J22x SH-J24 SH-J27 ZZ1 ZZ2 ZZ3 ZZ4 ZZ5 ZZ6 ZZ7
component class Logo: Logo1
component class "Mounting Holes": H1 H2 H3 H4
component class Header: J6 J24 J27
component class Screw: H10 H11 H12 H13
component class Shunt: SH-J21 SH-J24 SH-J27
differential pair CMLOUT: +CMLOUT_P -CMLOUT_N
differential pair CMLOUTC: +CMLOUTC_P -CMLOUTC_N
differential pair SER_DOUT: +SER_DOUT_P -SER_DOUT_N
differential pair FPD_DOUT: +FPD_DOUT_P -FPD_DOUT_N
differential pair FPD_DIN: +FPD_DIN_P -FPD_DIN_N
differential pair DOUT: +DOUT_P -DOUT_N
differential pair DIN: +DIN_P -DIN_N
differential pair DESER_DIN: +DESER_DIN_P -DESER_DIN_N

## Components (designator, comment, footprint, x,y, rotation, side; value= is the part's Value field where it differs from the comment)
C1 "GRM155R71A104KA01D" 0402 5895,4000 r270 bottom
C2 "GRM155R71A104KA01D" 0402 5895,3830 r90 bottom
C3 "GRM155R71A104KA01D" 0402 6173.62,4115 r0 bottom
C4 "GRM21BR71A106KE51L" 0805_HV 6200,4185 r0 bottom
C5 "GRM155R71A104KA01D" 0402 2900,2770 r90 top
C6 "EEV-FK1H331Q" SM_RADIAL_H13 2810,955 r180 top
C7 "EEV-FK1H331Q" SM_RADIAL_H13 3520,1525 r0 top
C8 "EEV-FK1H331Q" SM_RADIAL_H13 3520,955 r0 top
C9 "EEV-FK1H331Q" SM_RADIAL_H13 2810,1520 r180 top
C10 "GRM31CR71H475KA12L" 1206 3705,560 r90 top
C11 "GRM31CR71H475KA12L" 1206 3595,560 r90 top
C12 "GRM188R71H823KA93D" 0603#1 3505,590 r90 top
C13 "GRM188R71H222KA01D" 0603#1 3435,590 r90 top
C14 "GRM188R71E105KA12D" 0603#1 3790,2985 r90 top
C15 "GRM188R71E105KA12D" 0603#1 3730,2985 r90 top
C16 "GRM188R71E105KA12D" 0603#1 2930,2985 r90 top
C17 "GRM188R71E105KA12D" 0603#1 2870,2985 r90 top
C18 "GRM155R71A104KA01D" 0402 2960,2800 r90 top
C19 "GRM155R71A104KA01D" 0402 5970,3720 r0 bottom
C20 "GRM155R71C222KA01D" 0402 6050,4265 r90 bottom
C21 "GRM155R71C222KA01D" 0402 6100,4265 r90 bottom
C22 "GRM188R71A225KE15D" 0603#1 5970,4125 r0 bottom
C23 "GRM188R71A225KE15D" 0603#1 5840,3960 r90 bottom
C24 "GRM155R71A104KA01D" 0402 3210,2410 r270 top
C25 "GRM155R71A104KA01D" 0402 3500,2400 r270 top
C26 "GRM21BR71H105KA12L" 0805_HV 3315,2980 r0 bottom
C27 "C0603C102J5RACTU" 0603#1 2800,3420 r0 top
C28 "GRM21BR71H474KA88L" 0805_HV 2260,4360 r180 top
C29 "C0603C103J5RACTU" 0603#1 1090,4690 r180 top
C30 "GRM21BR71H105KA12L" 0805_HV 3315,2855 r90 bottom
C31 "GRM21BR71H474KA88L" 0805_HV 2160,4450 r180 top
C32 "C0603C102J5RACTU" 0603#1 2810,3365 r0 top
C33 "GRM21BR71H474KA88L" 0805_HV 2060,4360 r180 top
C34 "C0603C103J5RACTU" 0603#1 910,4690 r180 top
C35 "GRM155R71C224KA12D" 0402 3095,2410 r270 top
C36 "C0603C102J5RACTU" 0603#1 3210,3530 r270 top
C37 "GRM21BR71H474KA88L" 0805_HV 3020,4360 r180 top
C38 "C0603C103J5RACTU" 0603#1 2855,4690 r180 top
C39 "GRM21BR71H474KA88L" 0805_HV 2920,4450 r180 top
C40 "C0603C102J5RACTU" 0603#1 3050,3530 r270 top
C41 "GRM21BR71H474KA88L" 0805_HV 2820,4360 r180 top
C42 "C0603C103J5RACTU" 0603#1 2675,4690 r180 top
C43 "GRM155R71A104KA01D" 0402 3740,2615 r180 top
C44 "C0603C102J5RACTU" 0603#1 3620,3530 r270 top
C45 "GRM21BR71H474KA88L" 0805_HV 3770,4360 r180 top
C46 "C0603C103J5RACTU" 0603#1 3905,4690 r180 top
C47 "GRM21BR71H474KA88L" 0805_HV 3670,4450 r180 top
C48 "C0603C102J5RACTU" 0603#1 3460,3530 r270 top
C49 "GRM21BR71H474KA88L" 0805_HV 3570,4360 r180 top
C50 "C0603C103J5RACTU" 0603#1 3725,4690 r180 top
C51 "C0603C102J5RACTU" 0603#1 3855,3365 r180 top
C52 "GRM21BR71H474KA88L" 0805_HV 4540,4360 r180 top
C53 "C0603C103J5RACTU" 0603#1 5650,4690 r180 top
C54 "GRM21BR71H474KA88L" 0805_HV 4440,4450 r180 top
C55 "C0603C102J5RACTU" 0603#1 3765,3480 r180 top
C56 "GRM21BR71H474KA88L" 0805_HV 4340,4360 r180 top
C57 "C0603C103J5RACTU" 0603#1 5470,4690 r180 top
C58 "GRM155R71C103KA01D" 0402 5930,3200 r90 top
C59 "GRM155R71A104KA01D" 0402 5880,3200 r90 top
C60 "GRM21BR71C475KA73L" 0805_HV 5810,3075 r270 top
C61 "GRM155R71A104KA01D" 0402 5880,3095 r270 top
C62 "GRM155R71C103KA01D" 0402 6155,3375 r0 top
C63 "GRM155R71C104KA88D" 0402 5180,1815 r270 top
C64 "GRM21BR71C475KA73L" 0805_HV 5255,1805 r270 top
C65 "GRM155R71C104KA88D" 0402 5455,1820 r270 top
C66 "GRM21BR71C475KA73L" 0805_HV 5530,1800 r270 top
C67 "GRM155R71C103KA01D" 0402 6295,2965 r0 top
C68 "GRM155R71A104KA01D" 0402 6295,2920 r0 top
C69 "GRM155R71C103KA01D" 0402 5930,3095 r270 top
C70 "GRM155R71C103KA01D" 0402 6250,3340 r0 top
C71 "GRM155R71A104KA01D" 0402 6250,3340 r0 bottom
C72 "GRM155R71C103KA01D" 0402 6140,2945 r0 top
C73 "GRM155R71C103KA01D" 0402 6380,3180 r270 bottom
C74 "GRM155R71A104KA01D" 0402 6440,3180 r270 bottom
C75 "GRM21BR71C475KA73L" 0805_HV 6511.46,3190 r270 bottom
C76 "GRM155R71C103KA01D" 0402 6430,2980 r0 bottom
C77 "GRM155R71A104KA01D" 0402 6430,2930 r0 bottom
C78 "GRM31CR71A226KE15L" 1206 6470,2850 r0 bottom
C80 "C1005X7R1H104K050BB" 0402 6420,3040 r0 bottom
C81 "C1005X7R1H104K050BB" 0402 6420,3090 r180 bottom
C82 "DNI" 0603#1 6510,3100 r270 top
C84 "GRM188R71H104KA93D" 0603#1 6510,3163 r90 top
C85 "GRM188R71H104KA93D" 0603#1 6430,3166 r90 top
C86 "DNI" 0603#1 6430,3103 r270 top
C87 "GRM21BR71A106KE51L" 0805_HV 4850,1240 r90 bottom
C88 "GRM155R71A104KA01D" 0402 5025,1435 r90 top
C89 "GRM155R71C222KA01D" 0402 4845,1250 r180 top
C90 "GRM31CR72A105KA01L" 1206 1235,985 r270 bottom
C91 "GRM31CR71A226KE15L" 1206 1030,1270 r180 bottom
C92 "GRM31CR71H475KA12L" 1206 775,990 r180 bottom
C93 "GRM1885C1H151JA01D" 0603#1 805.59,1490 r0 bottom
C94 "GRM188R71H153KA01D" 0603#1 840,1590 r270 bottom
C95 "C1608X7R1C105K" 0603#1 746.5,1080 r180 bottom
C96 "GRM155R71A104KA01D" 0402 1039.19,2950.56 r180 bottom
C97 "GRM155R71C223KA01D" 0402 975,2875 r270 bottom
C98 "GRM31CR71H475KA12L" 1206 684,2919 r90 bottom
C99 "GRM155R71C103KA01D" 0402 1039.19,3050.56 r0 bottom
C100 "GRM31CR71A226KE15L" 1206 1335,2965 r90 bottom
C101 "GRM155R71A104KA01D" 0402 1045,3500 r180 bottom
C102 "GRM188R71A225KE15D" 0603#1 1160,3670 r270 bottom
C103 "GRM155R71C103KA01D" 0402 920,3675 r270 bottom
C104 "GRM155R71C103KA01D" 0402 6375,1360 r90 bottom
C105 "GRM155R71A104KA01D" 0402 6430,1360 r90 bottom
C106 "GRM21BR71C475KA73L" 0805_HV 6500,1390 r90 bottom
C107 "GRM155R71A104KA01D" 0402 5940,1475 r90 top
C108 "GRM155R71C103KA01D" 0402 5990,1475 r90 top
C109 "GRM188R71A105KA61D" 0603#1 2890,2695 r180 top
C110 "GRM188R71A105KA61D" 0603#1 6200,2945 r180 bottom
C111 "GRM188R71A105KA61D" 0603#1 6210,1150 r270 bottom
C112 "GRM155R71A104KA01D" 0402 655,3540 r180 top
C113 "GRM155R71C103KA01D" 0402 5990,1350 r270 top
C114 "GRM155R71A104KA01D" 0402 5940,1350 r270 top
C115 "GRM155R71C103KA01D" 0402 6340,1260 r270 bottom
C116 "GRM155R71A104KA01D" 0402 6390,1260 r270 bottom
C117 "GRM21BR71C475KA73L" 0805_HV 6465,1240 r270 bottom
C118 "GRM155R71C103KA01D" 0402 6400,1440 r0 bottom
C119 "GRM155R71A104KA01D" 0402 6400,1490 r0 bottom
C120 "GRM31CR71A226KE15L" 1206 6435,1570 r0 bottom
C122 "DNI" 0603#1 6510,1335 r270 top
C124 "GRM188R71H104KA93D" 0603#1 6510,1398 r90 top
C125 "GRM188R71H104KA93D" 0603#1 6430,1398 r90 top
C126 "DNI" 0603#1 6430,1335 r270 top
C127 "GRM155R71A104KA01D" 0402 4830,1331.65 r90 top
C128 "GRM155R71A104KA01D" 0402 5035,1060 r180 top
C129 "DNI" 0603#1 1215,1485 r180 top
C130 "GCM188R71H104KA57D" 0603#1 710,2125 r270 bottom
C131 "GRM21BR71A106KE51L" 0805_HV 1110,2075 r180 bottom
C132 "GRM21BR71C475KA73L" 0805_HV 933,1619 r90 bottom
D1 "SML-P12DTT86" LED_SMLP12_ORANGE 6870,3893.37 r90 top
D2 "SML-P12MTT86" SML-P1_YELLOW-GREEN 6790,3893.37 r90 top
D3 "MBRA160T3G" SMA 1155,1155 r0 bottom
D4 "SML-P12MTT86" SML-P1_YELLOW-GREEN 380,1050 r0 top
D5 "MBRA160T3G" SMA 870,2755 r180 bottom
D6 "SML-P12MTT86" SML-P1_YELLOW-GREEN 430,2990 r90 top
D7 "SML-P12MTT86" SML-P1_YELLOW-GREEN 465,3635 r270 top
D8 "SMLP12BC7TT86" LED_SMLP12_BLUE 5310,1120 r180 top
D9 "BAT54S-7-F" SOT-23 931,1468 r270 bottom
D10 "SML-P12MTT86" SML-P1_YELLOW-GREEN 435,1910 r90 top
FID1 "Fiducial" Fiducial10-20 6990,5490 r0 top
FID2 "Fiducial" Fiducial10-20 75,5470 r0 top
FID3 "Fiducial" Fiducial10-20 55,55 r0 top
FID4 "Fiducial" Fiducial10-20 6990,5490 r90 bottom
FID5 "Fiducial" Fiducial10-20 55,55 r90 bottom
FID6 "Fiducial" Fiducial10-20 75,5470 r90 bottom
H1 "DNI" "NY PMS 440 0025 PH" 200,4255 r0 top locked
H2 "DNI" "NY PMS 440 0025 PH" 6855,4255 r0 top locked
H3 "DNI" "NY PMS 440 0025 PH" 200,250 r0 top locked
H4 "DNI" "NY PMS 440 0025 PH" 6855,250 r0 top locked
H5 "4805" Keystone_1902C#1 200,4255 r180 bottom locked
H6 "4805" Keystone_1902C#1 6855,4255 r180 bottom locked
H7 "4805" Keystone_1902C#1 200,250 r180 bottom locked
H8 "4805" Keystone_1902C#1 6855,250 r180 bottom locked
H9 "HEATSINK_V5583K" HEATSINK_V5583K 3270,2770 r180 top locked
H10 "RM3X10MM 2701" BuildingFastener_MPMS_003_0005_PH 1748,2068 r180 bottom
H11 "RM3X10MM 2701" BuildingFastener_MPMS_003_0005_PH 1743,3469 r180 bottom
H12 "RM3X10MM 2701" BuildingFastener_MPMS_003_0005_PH 4803,2068 r180 bottom
H13 "RM3X10MM 2701" BuildingFastener_MPMS_003_0005_PH 4808,3469 r180 bottom
H14 "SRS-4-055" Keystone_1902C#2 1738,2069 r0 top
H15 "SRS-4-055" Keystone_1902C#2 1741,3470 r0 top
H16 "SRS-4-055" Keystone_1902C#2 4813,2069 r0 top
H17 "SRS-4-055" Keystone_1902C#2 4809,3470 r0 top
J1 "24V" CB35-36-CY 4025,435 r90 top
J2 "GND" CB35-36-CY 5050,435 r90 top
J3 "DIN PCM" Samtec_FTS-108-02-x-DV 5405,3563.52 r90 top
J4 "SJ-3523-SMT" CUI_SJ-3523-SMT 6650,5250 r270 top
J5 "Mute PCM" Samtec_FTS-104-02-x-DV 5637,4043 r90 top
J6 "Phase shedding" TSW-105-07-G-S 140,5080 r270 top
J7 "CH1" CONN_POMONA_2269-0 1000,5080 r180 top locked
J8 "DIN1 TAS" Samtec_FTS-108-02-x-DV 5405,3090 r90 top
J9 "CH2" CONN_POMONA_2269-0 2530,5080 r180 top locked
J10 "DIN2 TAS" Samtec_FTS-108-02-x-DV 5405,2615 r90 top
J11 "CH3" CONN_POMONA_2269-0 4050,5080 r180 top locked
J12 "CH4" CONN_POMONA_2269-0 5560,5080 r180 top locked
J13 "Addr DeSer" Samtec_FTS-104-02-x-DV 6010,900 r90 top
J14 "59S20X-400L5-Y" Rosenberger_59S20X-400L5 7010,2840 r0 top
J15 "651-305-142-821" CONN_USB-MINI-AB-651-305-142-821 6825,3330 r90 top
J16 "Addr TAS" Samtec_FTS-104-02-x-DV 2017,1319 r90 top
J17 "JTAG" CONN_SBH11-PBPC-D07-ST-BK 5970,220 r180 top
J18 "VBAT" CB35-36-CY 700,435 r90 top
J19 "Addr Ser" Samtec_FTS-104-02-x-DV 6398,4402.5 r90 top
J20 "GND" CB35-36-CY 1725,435 r90 top
J21 "Input Select" CONN_PEC03SAAN 169.87,2590.5 r90 top
J22 "FTS-124-01-L-DV" Samtec_FTS-124-01-x-DV 6290,2150 r90 top
J23 "59S20X-400L5-Y" Rosenberger_59S20X-400L5 7010,1090 r0 top
J24 "8V Ena" TSW-102-07-G-S 170,1155 r270 top
J25 "651-305-142-821" CONN_USB-MINI-AB-651-305-142-821 6825,1580 r90 top
J26 "CCH-J-02" CCH-J-02 6780,2485.04 r180 top
J27 "8V Ena" TSW-102-07-G-S 4375,990 r0 top
L1 "SER1360-103KLB" SER1360 3125,325 r270 top
L2 "1155EA-0001" HEAW 2160,4020 r180 top locked
L3 "1155EA-0001" HEAW 2920,4020 r180 top locked
L4 "1155EA-0001" HEAW 3680,4020 r180 top locked
L5 "1155EA-0001" HEAW 4440,4020 r180 top locked
L6 "BLM18AG102SN1" 0603#2 5365,1840 r0 top
L7 "BLM18AG102SN1" 0603#2 6480,3310 r0 bottom
L8 "BLM18AG102SN1" 0603#2 6310,2845 r0 bottom
L9 "100uH" MSS7341 6335,2585 r0 top
L10 "5.6uH" IND_1008PS 6395,2835 r180 top
L11 "KA4909-AL" KA4909 6130,3540 r180 top
L12 "DLW21SN261SQ2L" IND_DLW21S 6480,3315 r90 top
L13 "PF0552.683NL" PF055X_COUPLED 1175,985 r0 top
L14 "VLCF5028T-100M1R0-2" VLCF5028 1130,2815 r0 top
L16 "BLM18AG102SN1" 0603#2 6590,1310 r270 bottom
L17 "BLM18AG102SN1" 0603#2 6420,1675 r180 bottom
L18 "MSS7341T-104MLB" MSS7341 6420,780 r0 top
L19 "1008PS-562KL" IND_1008PS 6480,1020 r180 top
L20 "KA4909-AL" KA4909 6110,1690 r180 top
L21 "DLW21SN261SQ2L" IND_DLW21S 6480,1565 r90 top
LBL1 "Size: 0.65\" x 0.20 \"" Label_650x200 2406,198 r0 top
Logo1 "Texas Instruments" TI_Stacked_SolderMask_Small 865,4035 r0 top
R1 "CRCW040210K0JNED" 0402 5310,1270 r180 top
R2 "CRCW040210K0JNED" 0402 4850,1150 r0 top
R3 "CRCW0402133RFKED" 0402 5305,1170 r180 top
R4 "CRCW040210K0JNED" 0402 6175.16,3802.8 r270 top
R5 "CRCW040210K0JNED" 0402 6175,3920 r90 top
R6 "CRCW040210K0JNED" 0402 6072.8,3802.8 r270 top
R7 "CRCW0402470RJNED" 0402 6055,4143.62 r90 bottom
R8 "CRCW0402470RJNED" 0402 6100,4143.62 r90 bottom
R9 "CRCW040220K0JNED" 0402 3440,2400 r270 top
R10 "CRCW040247K0JNED" 0402 3160,2410 r270 top
R11 "RL1220S-5.6-F" 0805_HV 2925,3380 r90 top
R12 "RL1220S-5.6-F" 0805_HV 2835,3255 r90 top
R13 "RL1220S-5.6-F" 0805_HV 3290,3460 r90 top
R14 "RL1220S-5.6-F" 0805_HV 3130,3460 r90 top
R15 "RL1220S-5.6-F" 0805_HV 3540,3460 r90 top
R16 "RL1220S-5.6-F" 0805_HV 3380,3460 r90 top
R17 "RL1220S-5.6-F" 0805_HV 3825,3255 r90 top
R18 "RL1220S-5.6-F" 0805_HV 3735,3370 r90 top
R19 "CRCW040210K0JNED" 0402 6160,3385 r90 bottom
R20 "CRCW040210K0JNED" 0402 5925,2905 r180 bottom
R21 "CRCW040247K0JNED" 0402 3260,2410 r270 top
R22 "CRCW040247K0JNED" 0402 2910,2640 r180 top
R23 "CRCW04024K70JNED" 0402 6715,2240 r270 bottom
R24 "CRCW04024K70JNED" 0402 6765,2240 r270 bottom
R25 "CRCW040210K0JNED" 0402 6110,2895 r270 bottom
R26 "DNI" 0402 6270,410 r270 bottom
R27 "220" 0402 6170,410 r270 bottom
R28 "CRCW0402220RJNED" 0402 5770,410 r270 bottom
R29 "CRCW06031K00JNEA" 0603#1 6215,2785 r0 top
R30 "CRCW06031K00JNEA" 0603#1 6215,2860 r180 top
R31 "DNI" 0603#1 6478.5,2940 r180 top
R32 "CRCW040210K0JNED" 0402 1022,1489 r90 bottom
R33 "CRCW06030000Z0EA" 0603#1 6340,3600 r270 top
R34 "CRCW0402475RFKED" 0402 6870,3805 r270 top
R35 "CRCW0402365RFKED" 0402 6790,3803.62 r270 top
R36 "CRCW040210K0FKED" 0402 6230,2865 r270 bottom
R37 "CRCW06030000Z0EA" 0603#1 6340,3480 r90 top
R38 "CRCW04020000Z0ED" 0402 6325,4155 r90 top
R39 "CRCW040211K0FKED" 0402 6425,4155 r90 top
R40 "CRCW040249R9FKED" 0402 6405,3015 r0 top
R41 "CRCW040247K0JNED" 0402 4845,1200 r180 top
R43 "CRCW040210K0JNED" 0402 4880,1331.65 r90 top
R44 "CRCW06030000Z0EA" 0603#1 752,1010 r90 top
R45 "CRCW06030000Z0EA" 0603#1 1110,2225 r0 top
R46 "CRCW06031R00JNEA" 0603#1 1110,2155 r180 bottom
R47 "CRCW040249R9FKED" 0402 690,1610 r0 bottom
R48 "CRCW040210K0JNED" 0402 959,1367 r180 bottom
R49 "CRCW04021K96FKED" 0402 386.2,1130 r0 top
R50 "CRCW060311K5FKEA" 0603#1 775,1590 r270 bottom
R51 "CRCW04029K76FKED" 0402 690,1555 r180 bottom
R52 "CRCW04021K82FKED" 0402 690,1500 r0 bottom
R53 "CRCW040228K0FKED" 0402 690,1450 r0 bottom
R54 "CRCW040210K0JNED" 0402 6015,2880 r270 bottom
R56 "CRCW040244K2FKED" 0402 686.9,3040.56 r180 bottom
R57 "CRCW0402100KJNED" 0402 575,2870 r90 bottom
R58 "CRCW06030000Z0EA" 0603#1 1180,3155 r90 top
R59 "CRCW040210K0JNED" 0402 1039.19,3000.56 r180 bottom
R60 "CRCW04023K16FKED" 0402 950,3110 r0 bottom
R61 "ERJ-2BQFR39X" 0402 1265,2885 r270 bottom
R62 "CRCW0402365RFKED" 0402 375,3005 r90 top
R63 "CRCW04029K76FKED" 0402 900,3060 r0 bottom
R64 "CRCW06030000Z0EA" 0603#1 1115,3430 r180 top
R65 "CRCW06030000Z0EA" 0603#1 1230,3670 r270 top
R66 "CRCW0402365RFKED" 0402 380,1918.62 r90 top
R67 "CRCW0402365RFKED" 0402 535,3625 r270 top
R72 "CRCW04024K70JNED" 0402 6715,2060 r90 bottom
R73 "CRCW04024K70JNED" 0402 6765,2060 r90 bottom
R74 "CRCW040210K0JNED" 0402 6355,1145 r270 bottom
R86 "CRCW06031K00JNEA" 0603#1 6295,980 r0 top
R87 "CRCW06031K00JNEA" 0603#1 6295,1050 r180 top
R88 "DNI" 0603#1 6485,1150 r180 top
R89 "CRCW040210K0FKED" 0402 6155,1170 r270 bottom
R90 "CRCW04022K00FKED" 0402 5985,650 r90 top
R91 "CRCW04020000Z0ED" 0402 5935,650 r90 top
R92 "CRCW040210K0JNED" 0402 6265,1165 r270 bottom
R93 "CRCW06030000Z0EA" 0603#1 6320,1750 r270 top
R94 "CRCW0402100KJNED" 0402 6310,1145 r90 bottom
R95 "CRCW06030000Z0EA" 0603#1 6320,1630 r90 top
R96 "CRCW040249R9FKED" 0402 6405,1245 r0 top
R97 "CRCW040210K0FKED" 0402 2045,1154 r180 bottom
R98 "CRCW04025K36FKED" 0402 1970,1124 r180 top
R99 "CRCW040210K0FKED" 0402 2095,1099 r270 top
R100 "CRCW040218K7FKED" 0402 2015,1074 r180 top
R103 "CRCW0402100KFKED" 0402 6475,4158.62 r90 top
R104 "CRCW04023K01FKED" 0402 6375,4155 r90 top
R105 "CRCW0402100KFKED" 0402 6085,650 r90 top
R106 "CRCW040214K0FKED" 0402 6035,650 r90 top
R107 "CRCW040210K0JNED" 0402 6021.61,3802.8 r270 top
R108 "CRCW06030000Z0EA" 0603#1 1215,1410 r0 top
S1 "S1" SW_SKRKAEE010 4075,1312.32 r270 top
S5 "RST" SW_SKRKAEE010 4520,1315 r270 top
SH-J3 "NPB02SVFN-RC" NPB02SVFN-RC 5330,3565 r90 top
SH-J5 "NPB02SVFN-RC" NPB02SVFN-RC 6320,4400 r90 top
SH-J8 "NPB02SVFN-RC" NPB02SVFN-RC 5225,3090 r90 top
SH-J10 "NPB02SVFN-RC" NPB02SVFN-RC 5280,2615 r90 top
SH-J13 "NPB02SVFN-RC" NPB02SVFN-RC 5935,900 r90 top
SH-J16 "NPB02SVFN-RC" NPB02SVFN-RC 1940,1320 r90 top
SH-J19 "NPB02SVFN-RC" NPB02SVFN-RC 5560,4040 r90 top
SH-J21 "969102-0000-DA" SNT-100-BK-G 170,2540 r90 top
SH-J22a "NPB02SVFN-RC" NPB02SVFN-RC 5715,2150 r90 top
SH-J22b "NPB02SVFN-RC" NPB02SVFN-RC 5765,2150 r90 top
SH-J22c "NPB02SVFN-RC" NPB02SVFN-RC 5815,2150 r90 top
SH-J22d "NPB02SVFN-RC" NPB02SVFN-RC 5865,2150 r90 top
SH-J22e "NPB02SVFN-RC" NPB02SVFN-RC 5915,2150 r90 top
SH-J22f "NPB02SVFN-RC" NPB02SVFN-RC 5965,2150 r90 top
SH-J22g "NPB02SVFN-RC" NPB02SVFN-RC 6015,2150 r90 top
SH-J22h "NPB02SVFN-RC" NPB02SVFN-RC 6065,2150 r90 top
SH-J22i "NPB02SVFN-RC" NPB02SVFN-RC 6115,2150 r90 top
SH-J22j "NPB02SVFN-RC" NPB02SVFN-RC 6165,2150 r90 top
SH-J22k "NPB02SVFN-RC" NPB02SVFN-RC 6215,2150 r90 top
SH-J22l "NPB02SVFN-RC" NPB02SVFN-RC 6265,2150 r90 top
SH-J22m "NPB02SVFN-RC" NPB02SVFN-RC 6315,2150 r90 top
SH-J22n "NPB02SVFN-RC" NPB02SVFN-RC 6365,2150 r90 top
SH-J22o "NPB02SVFN-RC" NPB02SVFN-RC 6415,2150 r90 top
SH-J22p "NPB02SVFN-RC" NPB02SVFN-RC 6465,2150 r90 top
SH-J22q "NPB02SVFN-RC" NPB02SVFN-RC 6515,2150 r90 top
SH-J22r "NPB02SVFN-RC" NPB02SVFN-RC 6565,2150 r90 top
SH-J22s "NPB02SVFN-RC" NPB02SVFN-RC 6615,2150 r90 top
SH-J22t "NPB02SVFN-RC" NPB02SVFN-RC 6665,2150 r90 top
SH-J22u "NPB02SVFN-RC" NPB02SVFN-RC 6715,2150 r90 top
SH-J22v "NPB02SVFN-RC" NPB02SVFN-RC 6765,2150 r90 top
SH-J22w "NPB02SVFN-RC" NPB02SVFN-RC 6815,2150 r90 top
SH-J22x "NPB02SVFN-RC" NPB02SVFN-RC 6865,2150 r90 top
SH-J24 "969102-0000-DA" SNT-100-BK-G 170,1155 r90 top
SH-J27 "969102-0000-DA" SNT-100-BK-G 4375,990 r0 top
TP1 "24V" Keystone5005 4400,500 r0 top
TP2 "GND" Keystone5006 4660,500 r0 top
TP3 "GND" Keystone5006 4985,3945 r180 top
TP4 "GND" Keystone5006 1600,3950 r180 top
TP5 "CLIP_OTW" Keystone5007 4505,1710 r0 top
TP6 "FAULT" Keystone5007 4160,1710 r0 top
TP7 "SCL" Keystone5007 6620,4020 r0 top
TP8 "SDA" Keystone5007 6620,3740 r0 top
TP9 "GND" Keystone5006 4840,1710 r180 top
TP10 "VBAT" Keystone5005 1100,500 r180 top
TP11 "8V" Keystone5005 168,808 r90 top
TP12 "COMP_P" Keystone5009 770,1735 r0 top
TP13 "COMP_M" Keystone5008 610,1735 r0 top
TP14 "GND" Keystone5006 1350,500 r180 top
TP15 "VIN" Keystone5005 169.87,2250.5 r90 top
TP16 "3V3" Keystone5005 170,3030 r90 top
TP17 "GND" Keystone5006 170,3400 r90 top
TP18 "1V8" Keystone5005 170,3750 r90 top
TP19 "3V3_MCU" Keystone5005 159.87,1890.5 r90 top
TP23 "SCL" Keystone5007 5690,930 r0 top
TP24 "SDA" Keystone5007 5395,930 r0 top
TP37 "GPO3" Keystone5007 5600,1385 r0 top
TP38 "GPO2" Keystone5007 5740,1205 r0 top
TP41 "GND" Keystone5006 169.87,1510.5 r90 top
TP48 "GND" Keystone5006 6800,700 r90 top
TP54 "GPI2" Keystone5007 5195,2160 r90 top
TP55 "GPI3" Keystone5007 5375,2160 r90 top
U1 "PCM5102AQPWRQ1" PW0020A_N 6060,3915 r270 bottom
U2 "*" PBH0064A_N 3330.32,2820 r90 top locked
U3 "DS90UA102TRHSRQ1" RHS0048A 6150,3150 r270 top locked
U6 "MSP430F2252TRHARQ1" RHA0040B 5090,1240 r0 top
U7 "LM5001IDRQ1" D0008A 805.59,1270 r90 bottom
U8 "LM34919CQSD" DNT0012B 846.9,2940.56 r0 bottom
U9 "TPS79318DBVRQ1" DBV0005A 1033.76,3645.67 r90 bottom
U10 "DS90UA101TRTVTQ1" RTV0032A 6180,1370 r90 top locked
U13 "LM2936QMM-3.3/NOPB" MUA08A_N 890,2110 r180 bottom
U14 "CAHCT1G125QDCKRQ1" DCK0005A 645,3630 r270 top
ZZ1 "This Assembly Note is for PCB labels only" AssemblyNoteLabel 55,6215 r0 top
ZZ2 "These assemblies are ESD sensitive, ESD precautions shall be observed." AssemblyNote 55,6129.11 r0 top
ZZ3 "These assemblies must be clean and free from flux and all contaminants. Use of no clean flux is not acceptable." AssemblyNote 55,6040.56 r0 top
ZZ4 "These assemblies must comply with workmanship standards IPC-A-610 Class 2, unless otherwise specified." AssemblyNote 55,5952 r0 top
ZZ5 "Apply a thin layer of heatsink grease on top of U2 before installing heatsink" AssemblyNote 55,5860 r0 top
ZZ6 "When installing J7, J8, J11, and J12, do not install the bottom-side insulator. Nuts must contact bottom copper pads." AssemblyNote 55,5770 r0 top
ZZ7 "When installing J1, J2, J18, and J20, solder AND bolt them" AssemblyNote 55,5685 r0 top

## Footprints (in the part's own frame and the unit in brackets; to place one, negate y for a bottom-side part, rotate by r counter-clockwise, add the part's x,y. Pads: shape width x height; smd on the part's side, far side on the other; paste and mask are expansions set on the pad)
0402 [mm] "0402 from SM-752 data"
  rect 0.8x0.6 smd: 1(-0.6,0) 2(0.6,0)
  silkscreen extent -1.22,-0.52 1.22,0.52, body extent -0.55,-0.3 0.55,0.3, height 0.6
0603#1 [mm] "0603 from SM-752 data"
  rect 1x0.95 smd: 1(-0.8,0) 2(0.8,0)
  silkscreen extent -1.52,-0.69 1.52,0.69, body extent -0.87,-0.47 0.87,0.47, height 0.85
0603#2 [mm]
  rect 0.762x1.016 smd mask+0.051: 1(-0.889,0) 2(0.889,0)
0805_HV [mil] "0805 with 30mil clearance between pads"
  rect 50x63 smd: 1(-40,0) 2(40,0)
  silkscreen extent -74,-40 74,40, body extent -43,-29 43,29, height 43
1206 [mm] "1206 from SM-752 data"
  rect 1.3x1.85 smd: 1(-1.45,0) 2(1.45,0)
  silkscreen extent -2.4,-1.21 2.4,1.21, body extent -1.7,-0.9 1.7,0.9, height 1.35
AssemblyNote [mil] "Assembly Note"
AssemblyNoteLabel [mil] "Assembly Note for PCB Labels"
BuildingFastener_MPMS_003_0005_PH [mil] "MACHINE SCREW PAN PHILLIPS M3"
  round 1 on Mech4: 0(0,0)
  body extent -118,-118 118,118, height 93
CB35-36-CY [mil] "Terminal 50A Lug"
  rect 550x380 hole 188 copper offset -45,0 paste-190: 1(0,0)
  body extent -960,-189 230,191, height 614
CCH-J-02 [mm] "Double Compliant Coax Assembly"
  round 0.65 hole 0.25 mask+0: 1(-3.3,0) 2(3.3,0)
  round 0.66 hole 0.406 mask+0: 1A(-3.3,1.27) 2A(3.3,1.27)
  round 1.7 hole 1.7 mask+0: MH1(0,2.16) MH2(0,-2.16)
  Top Layer region: -0.76,0 -1.012,1.102 -1.716,1.986 -2.735,2.476 -3.865,2.476 -4.884,1.986 -5.588,1.102 -5.84,0 -5.84,0 -4,0 -3.931,0.304 -3.736,0.547 -3.456,0.682 -3.144,0.682 -2.864,0.547 -2.669,0.304 -2.6,0 -2.6,0
  Top Layer region: -5.84,0 -5.588,-1.102 -4.884,-1.986 -3.865,-2.476 -2.735,-2.476 -1.716,-1.986 -1.012,-1.102 -0.76,0 -0.76,0 -2.6,0 -2.669,-0.304 -2.864,-0.547 -3.144,-0.682 -3.456,-0.682 -3.736,-0.547 -3.931,-0.304 -4,0 -4,0
  Top Layer region: 5.84,0 5.588,1.102 4.884,1.986 3.865,2.476 2.735,2.476 1.716,1.986 1.012,1.102 0.76,0 0.76,0 2.6,0 2.669,0.304 2.864,0.547 3.144,0.682 3.456,0.682 3.736,0.547 3.931,0.304 4,0 4,0
  Top Layer region: 0.76,0 1.012,-1.102 1.716,-1.986 2.735,-2.476 3.865,-2.476 4.884,-1.986 5.588,-1.102 5.84,0 5.84,0 4,0 3.931,-0.304 3.736,-0.547 3.456,-0.682 3.144,-0.682 2.864,-0.547 2.669,-0.304 2.6,0 2.6,0
  silkscreen extent -6.35,-4.19 6.35,4.19
CONN_PEC03SAAN [mm] "SULLINS"
  rect 1.5x1.5 hole 1.016: 1(-2.54,0)
  round 1.5 hole 1.016: 2(0,0) 3(2.54,0)
  silkscreen extent -4.72,-1.27 3.81,1.27, body extent -3.84,-1.3 3.84,1.3, height 8.38
CONN_POMONA_2269-0 [mil]
  round 500 hole 265: 1(-375,0) 2(375,0)
  silkscreen extent -698,-323 698,323, body extent -688,-315 688,315, height 351
CONN_SBH11-PBPC-D07-ST-BK [mm] "Sullins recommended land pattern"
  rect 1.65x1.65 hole 1.016 mask+0: 1(-7.62,-1.27)
  round 1.65 hole 1.016 mask+0: 2(-7.62,1.27) 3(-5.08,-1.27) 4(-5.08,1.27) 5(-2.54,-1.27) 6(-2.54,1.27) 7(0,-1.27) 8(0,1.27) 9(2.54,-1.27) 10(2.54,1.27) 11(5.08,-1.27) 12(5.08,1.27) 13(7.62,-1.27) 14(7.62,1.27)
  silkscreen extent -12.64,-5.08 12.64,4.7, body extent -12.64,-4.4 12.64,4.7, height 9.12
CONN_USB-MINI-AB-651-305-142-821 [mm] "WE-USB2-MINI-AB TYPE"
  rect 0.5x2.3 smd: 1(-1.6,2.8) 2(-0.8,2.8) 3(0,2.8) 4(0.8,2.8) 5(1.6,2.8)
  rect 2x2.5 smd: 6(4.45,2.7) 7(4.45,-2.8) 8(-4.45,-2.8) 9(-4.45,2.7)
  silkscreen extent -4.03,-5.6 4,1.1, body extent -4.95,-5.72 4.95,3.68, height 4.12
CUI_SJ-3523-SMT [mm] "CUI recommended land pattern Rev C CUI_SJ-3523-SMT_Datasheet.pdf"
  rect 2.2x2.8 smd: 1(-4.7,-3.7) 3(-2.7,3.7)
  rect 2.8x2.8 smd: 2(4.7,-3.7)
  round 0 hole 1.7 unplated: 4(-3.6,0) 5(3.4,0)
  silkscreen extent -9.9,-3.2 7.6,3.2, body extent -9.6,-4.5 7.4,4.5, height 5.12
D0008A [mm] "SOIC, 8-Leads, Body 4.9x3.9mm, Pitch 1.27mm, IPC Low Density"
  oval 2.5x0.7 smd: 1(-2.45,1.905) 2(-2.45,0.635) 3(-2.45,-0.635) 4(-2.45,-1.905) 5(2.45,-1.905) 6(2.45,-0.635) 7(2.45,0.635) 8(2.45,1.905)
  silkscreen extent -0.9,-2.5 0.9,2.5, body extent -3,-2.45 3,2.45, height 1.63
DBV0005A [mm] "SOT23, 5-Leads, Body 2.9x1.6mm, Pitch 0.95mm, Lead Span 2.8mm, IPC Low Density"
  rect 1.3x0.7 smd: 1(-1.2,0.95) 2(-1.2,0) 3(-1.2,-0.95) 4(1.2,-0.95) 5(1.2,0.95)
  silkscreen extent -0.15,-1.55 0.15,1.55, body extent -1.42,-1.46 1.42,1.46, height 1.08
DCK0005A [mm] "SOT353, 5-Leads, Body 2x1.3mm, Pitch 0.65mm, Lead Span 2.1mm, IPC Low Density"
  rect 1.05x0.45 smd: 1(-0.95,0.65) 2(-0.95,0) 3(-0.95,-0.65) 4(0.95,-0.65) 5(0.95,0.65)
  silkscreen extent -0.05,-1.1 0.05,1.1, body extent -1.14,-1 1.14,1, height 0.94
DNT0012B [mm] "SON, 12-Leads, Body 4x4mm, Pitch 0.5mm"
  rect 0.6x0.25 smd: 1(-1.9,1.25) 2(-1.9,0.75) 3(-1.9,0.25) 4(-1.9,-0.25) 5(-1.9,-0.75) 6(-1.9,-1.25) 7(1.9,-1.25) 8(1.9,-0.75) 9(1.9,-0.25) 10(1.9,0.25) 11(1.9,0.75) 12(1.9,1.25)
  rect 2.6x3 smd paste-1.3: 13(0,0)
  silkscreen extent -2.2,-2.2 2.2,2.2, body extent -2.05,-2.05 2.05,2.05, height 0.81
Fiducial10-20 [mm]
  round 1 smd paste-0.5 mask+0.5: 1(0,0)
  Top Layer keep-out circle w1.178: c0,0 r0.5
HEATSINK_V5583K [mil] "Assmann"
  silkscreen extent -1791,-925 1791,925, body extent -1780,-913 1780,913, height 1299
HEAW [mm] "TOKO"
  rect 4.5x2.8 smd: 1(-5.7,3.55) 2(-5.7,-3.55) 3(5.7,-3.55) 4(5.7,3.55)
  silkscreen extent -8.66,-6.65 7.15,6.65, body extent -7.15,-6.65 7.15,6.65, height 10.51
IND_1008PS [mil]
  rect 60x100 smd: 1(-50,0) 2(50,0)
IND_DLW21S [mm] "muRata"
  rect 0.4x0.9 smd: 1(-0.45,0.85) 2(-0.45,-0.85) 3(0.45,-0.85) 4(0.45,0.85)
  silkscreen extent -0.96,0.88 -0.92,0.92, body extent -0.7,-1.1 0.7,1.1, height 1.41
KA4909 [mm] "Coilcraft"
  rect 1.52x1.27 smd: 1(-2.925,2.54) 2(-2.925,0) 3(-2.925,-2.54) 4(2.925,-2.54) 5(2.925,0) 6(2.925,2.54)
  silkscreen extent -4.3,-3.34 3.48,3.34, body extent -3.48,-3.34 3.48,3.34, height 4.66
Keystone5005 [mil] "Keystone Compact loops"
  round 87 hole 63: 1(0,0)
  silkscreen extent -70,-70 70,70, body extent -63,-63 62,63, height 225
Keystone5006 [mil] "Keystone Compact loops"
  round 87 hole 63: 1(0,0)
  silkscreen extent -70,-70 70,70, body extent -63,-63 62,63, height 225
Keystone5007 [mil] "Keystone Compact loops"
  round 87 hole 63: 1(0,0)
  silkscreen extent -70,-70 70,70, body extent -63,-63 62,63, height 225
Keystone5008 [mil] "Keystone Compact loops"
  round 87 hole 63: 1(0,0)
  silkscreen extent -70,-70 70,70, body extent -63,-63 62,63, height 225
Keystone5009 [mil] "Keystone Compact loops"
  round 87 hole 63: 1(0,0)
  silkscreen extent -70,-70 70,70, body extent -63,-63 62,63, height 225
Keystone_1902C#1 [mil] "Hex Standoff, 4-40 threaded, nylon"
  body extent -145,-126 146,126, height 501
Keystone_1902C#2 [mil] "Hex Standoff, 4-40 threaded, nylon"
  round 1 on Mech3: 0(0,0)
  body extent -145,-126 146,126, height 501
Label_650x200 [mil] "Thermal Transfer Label"
  silkscreen extent -325,-100 325,100, body extent -326,-101 326,101, height 1
LED_SMLP12_BLUE [mm] "Rohm Semiconductor"
  rect 0.5x0.6 smd mask+0.08: 1(-0.45,0) 2(0.45,0)
  silkscreen extent 0.92,-0.3 0.92,0.3, body extent -0.55,-0.35 0.55,0.35, height 0.25
LED_SMLP12_ORANGE [mm] "Rohm Semiconductor"
  rect 0.5x0.6 smd mask+0.08: 1(-0.45,0) 2(0.45,0)
  silkscreen extent 0.92,-0.3 0.92,0.3, body extent -0.55,-0.35 0.55,0.35, height 0.25
MSS7341 [mil] "Coilcraft recommended land pattern Document 383-2 1/3/11"
  rect 28.54x280 smd: 1(-125.49,0) 2(125.49,0)
  Top Layer region: -41.34,-139.76 -41.34,-101.16 -41.33,-101.13 -82.83,-71.24 -106.18,-25.72 -106.25,25.43 -83.02,71.01 -41.6,101.02 -41.6,101.02 -41.34,101.02 -41.34,139.76 -139.76,139.76 -139.76,-139.76
  Top Layer region: 41.34,-139.76 41.34,-101.16 41.33,-101.13 82.83,-71.24 106.18,-25.72 106.25,25.43 83.02,71.01 41.6,101.02 41.6,101.02 41.34,101.02 41.34,139.76 139.76,139.76 139.76,-139.76
  silkscreen extent -152,-154 151,154, body extent -149,-149 149,149, height 162
MUA08A_N [mm] "TSOP, 8-Leads, Body 3x3mm, Pitch 0.65mm, IPC Medium Density"
  oval 1.7x0.45 smd: 1(-2.1,0.975) 2(-2.1,0.325) 3(-2.1,-0.325) 4(-2.1,-0.975) 5(2.1,-0.975) 6(2.1,-0.325) 7(2.1,0.325) 8(2.1,0.975)
  silkscreen extent -2.22,-1.55 0.85,1.87, body extent -1.6,-1.6 1.6,1.6, height 1.09
NPB02SVFN-RC [mil] "CONN JUMPER SHORTING 1.27MM GOLD"
  body extent -55,-31 55,31, height 226
"NY PMS 440 0025 PH" [mm] "4-40 nylon screw and mounting hole"
  round 8 hole 3.2: 1(0,0)
  body extent -3.3,-3.3 3.3,3.3, height 2.69
PBH0064A_N [mm] "TQFP, 64-Leads, Body 16.2x16.2mm (max), Pitch 0.80mm, IPC Medium Density"
  oval 1.7x0.5 smd: 1(-7.65,6) 2(-7.65,5.2) 3(-7.65,4.4) 4(-7.65,3.6) 5(-7.65,2.8) 6(-7.65,2) 7(-7.65,1.2) 8(-7.65,0.4) 9(-7.65,-0.4) 10(-7.65,-1.2) 11(-7.65,-2) 12(-7.65,-2.8) 13(-7.65,-3.6) 14(-7.65,-4.4) 15(-7.65,-5.2) 16(-7.65,-6) 33(7.65,-6) 34(7.65,-5.2) 35(7.65,-4.4) 36(7.65,-3.6) 37(7.65,-2.8) 38(7.65,-2) 39(7.65,-1.2) 40(7.65,-0.4) 41(7.65,0.4) 42(7.65,1.2) 43(7.65,2) 44(7.65,2.8) 45(7.65,3.6) 46(7.65,4.4) 47(7.65,5.2) 48(7.65,6)
  oval 0.5x1.7 smd: 17(-6,-7.65) 18(-5.2,-7.65) 19(-4.4,-7.65) 20(-3.6,-7.65) 21(-2.8,-7.65) 22(-2,-7.65) 23(-1.2,-7.65) 24(-0.4,-7.65) 25(0.4,-7.65) 26(1.2,-7.65) 27(2,-7.65) 28(2.8,-7.65) 29(3.6,-7.65) 30(4.4,-7.65) 31(5.2,-7.65) 32(6,-7.65) 49(6,7.65) 50(5.2,7.65) 51(4.4,7.65) 52(3.6,7.65) 53(2.8,7.65) 54(2,7.65) 55(1.2,7.65) 56(0.4,7.65) 57(-0.4,7.65) 58(-1.2,7.65) 59(-2,7.65) 60(-2.8,7.65) 61(-3.6,7.65) 62(-4.4,7.65) 63(-5.2,7.65) 64(-6,7.65)
  silkscreen extent -7.77,-6.4 6.4,6.92, body extent -7,-7 7,7, height 1.48
PF055X_COUPLED [mm] "Pulse coupled inductors"
  rect 3.53x2.54 smd mask+0.051: 1(-4.94,1.515) 2(-4.94,-1.515) 3(4.94,-1.515) 4(4.94,1.515)
  silkscreen extent -6.83,-6.25 6.25,6.25, body extent -6.25,-6.25 6.25,6.25, height 8
PW0020A_N [mm] "TSOP, 20-Leads, Body 6.5x4.4mm, Pitch 0.65mm, IPC Medium Density"
  oval 1.7x0.35 smd: 1(-2.85,2.925) 2(-2.85,2.275) 3(-2.85,1.625) 4(-2.85,0.975) 5(-2.85,0.325) 6(-2.85,-0.325) 7(-2.85,-0.975) 8(-2.85,-1.625) 9(-2.85,-2.275) 10(-2.85,-2.925) 11(2.85,-2.925) 12(2.85,-2.275) 13(2.85,-1.625) 14(2.85,-0.975) 15(2.85,-0.325) 16(2.85,0.325) 17(2.85,0.975) 18(2.85,1.625) 19(2.85,2.275) 20(2.85,2.925)
  silkscreen extent -1.6,-3.3 1.6,3.3, body extent -3.21,-3.25 3.21,3.25, height 0.99
RHA0040B [mm] "QFN, 40-Leads, Body 6x6mm, Pitch 0.5mm, Thermal Pad 4.15 x 4.15mm, TI Recommended"
  oval 0.6x0.23 smd mask+0.07: 1(-2.9,2.25) 2(-2.9,1.75) 3(-2.9,1.25) 4(-2.9,0.75) 5(-2.9,0.25) 6(-2.9,-0.25) 7(-2.9,-0.75) 8(-2.9,-1.25) 9(-2.9,-1.75) 10(-2.9,-2.25) 21(2.9,-2.25) 22(2.9,-1.75) 23(2.9,-1.25) 24(2.9,-0.75) 25(2.9,-0.25) 26(2.9,0.25) 27(2.9,0.75) 28(2.9,1.25) 29(2.9,1.75) 30(2.9,2.25)
  oval 0.23x0.6 smd mask+0.07: 11(-2.25,-2.9) 12(-1.75,-2.9) 13(-1.25,-2.9) 14(-0.75,-2.9) 15(-0.25,-2.9) 16(0.25,-2.9) 17(0.75,-2.9) 18(1.25,-2.9) 19(1.75,-2.9) 20(2.25,-2.9) 31(2.25,2.9) 32(1.75,2.9) 33(1.25,2.9) 34(0.75,2.9) 35(0.25,2.9) 36(-0.25,2.9) 37(-0.75,2.9) 38(-1.25,2.9) 39(-1.75,2.9) 40(-2.25,2.9)
  rect 4.15x4.15 smd paste-2.1 mask+0.07: 41(0,0)
  silkscreen extent -3.22,2.79 -2.79,3.22, body extent -3.08,-3.08 3.08,3.08, height 1.01
RHS0048A [mm] "QFN, 48-Leads, Body 7x7mm, Pitch 0.5mm, TI Recommended"
  rect 0.6x0.25 smd mask+0.051: 1(-3.4,2.75) 2(-3.4,2.25) 3(-3.4,1.75) 4(-3.4,1.25) 5(-3.4,0.75) 6(-3.4,0.25) 7(-3.4,-0.25) 8(-3.4,-0.75) 9(-3.4,-1.25) 10(-3.4,-1.75) 11(-3.4,-2.25) 12(-3.4,-2.75) 25(3.4,-2.75) 26(3.4,-2.25) 27(3.4,-1.75) 28(3.4,-1.25) 29(3.4,-0.75) 30(3.4,-0.25) 31(3.4,0.25) 32(3.4,0.75) 33(3.4,1.25) 34(3.4,1.75) 35(3.4,2.25) 36(3.4,2.75)
  rect 0.25x0.6 smd mask+0.051: 13(-2.75,-3.4) 14(-2.25,-3.4) 15(-1.75,-3.4) 16(-1.25,-3.4) 17(-0.75,-3.4) 18(-0.25,-3.4) 19(0.25,-3.4) 20(0.75,-3.4) 21(1.25,-3.4) 22(1.75,-3.4) 23(2.25,-3.4) 24(2.75,-3.4) 37(2.75,3.4) 38(2.25,3.4) 39(1.75,3.4) 40(1.25,3.4) 41(0.75,3.4) 42(0.25,3.4) 43(-0.25,3.4) 44(-0.75,3.4) 45(-1.25,3.4) 46(-1.75,3.4) 47(-2.25,3.4) 48(-2.75,3.4)
  rect 5.1x5.1 smd paste-2.55 mask+0.076: 49(0,0)
  silkscreen extent -3.85,3.27 -3.27,3.85, body extent -3.55,-3.55 3.55,3.55, height 0.81
Rosenberger_59S20X-400L5 [mm] "Rosenberger"
  rect 2x2 hole 1.5 paste+0: 1(-4.55,0)
  round 2.4 hole 1.9 paste+0: MH1(-7.09,2.54) MH2(-2.01,2.54) MH3(-2.01,-2.54) MH4(-7.09,-2.54)
  silkscreen extent -8.3,-4.25 8.3,4.25, body extent -8.3,-4.25 8.3,4.25, height 11.61
RTV0032A [mm] "QFN, 32-Leads, Body 5x5mm, Pitch 0.5mm"
  rect 0.6x0.25 smd mask+0.051: 1(-2.4,1.75) 2(-2.4,1.25) 3(-2.4,0.75) 4(-2.4,0.25) 5(-2.4,-0.25) 6(-2.4,-0.75) 7(-2.4,-1.25) 8(-2.4,-1.75) 17(2.4,-1.75) 18(2.4,-1.25) 19(2.4,-0.75) 20(2.4,-0.25) 21(2.4,0.25) 22(2.4,0.75) 23(2.4,1.25) 24(2.4,1.75)
  rect 0.25x0.6 smd mask+0.051: 9(-1.75,-2.4) 10(-1.25,-2.4) 11(-0.75,-2.4) 12(-0.25,-2.4) 13(0.25,-2.4) 14(0.75,-2.4) 15(1.25,-2.4) 16(1.75,-2.4) 25(1.75,2.4) 26(1.25,2.4) 27(0.75,2.4) 28(0.25,2.4) 29(-0.25,2.4) 30(-0.75,2.4) 31(-1.25,2.4) 32(-1.75,2.4)
  rect 3.1x3.1 smd paste-1.55 mask+0.051: 33(0,0)
  silkscreen extent -3.52,-2.85 2.85,2.85, body extent -2.55,-2.55 2.55,2.55, height 0.81
Samtec_FTS-104-02-x-DV [mm] "Samtec"
  rect 3.125x0.74 smd: 1(-1.867,1.905) 2(1.867,1.905) 3(-1.867,0.635) 4(1.867,0.635) 5(-1.867,-0.635) 6(1.867,-0.635) 7(-1.867,-1.905) 8(1.867,-1.905)
  silkscreen extent -2.41,-2.54 1.71,3.05, body extent -2.92,-2.54 2.92,2.54, height 2.93
Samtec_FTS-108-02-x-DV [mm] "Samtec"
  rect 3.125x0.74 smd: 1(-1.867,4.445) 2(1.867,4.445) 3(-1.867,3.175) 4(1.867,3.175) 5(-1.867,1.905) 6(1.867,1.905) 7(-1.867,0.635) 8(1.867,0.635) 9(-1.867,-0.635) 10(1.867,-0.635) 11(-1.867,-1.905) 12(1.867,-1.905) 13(-1.867,-3.175) 14(1.867,-3.175) 15(-1.867,-4.445) 16(1.867,-4.445)
  silkscreen extent -2.41,-5.08 1.71,5.46, body extent -2.92,-5.08 2.92,5.08, height 3.19
Samtec_FTS-124-01-x-DV [mm] "Samtec"
  rect 3.125x0.74 smd: 1(-1.867,14.605) 2(1.867,14.605) 3(-1.867,13.335) 4(1.867,13.335) 5(-1.867,12.065) 6(1.867,12.065) 7(-1.867,10.795) 8(1.867,10.795) 9(-1.867,9.525) 10(1.867,9.525) 11(-1.867,8.255) 12(1.867,8.255) 13(-1.867,6.985) 14(1.867,6.985) 15(-1.867,5.715) 16(1.867,5.715) 17(-1.867,4.445) 18(1.867,4.445) 19(-1.867,3.175) 20(1.867,3.175) 21(-1.867,1.905) 22(1.867,1.905) 23(-1.867,0.635) 24(1.867,0.635) 25(-1.867,-0.635) 26(1.867,-0.635) 27(-1.867,-1.905) 28(1.867,-1.905) 29(-1.867,-3.175) 30(1.867,-3.175) 31(-1.867,-4.445) 32(1.867,-4.445) 33(-1.867,-5.715) 34(1.867,-5.715) 35(-1.867,-6.985) 36(1.867,-6.985) 37(-1.867,-8.255) 38(1.867,-8.255) 39(-1.867,-9.525) 40(1.867,-9.525) 41(-1.867,-10.795) 42(1.867,-10.795) 43(-1.867,-12.065) 44(1.867,-12.065) 45(-1.867,-13.335) 46(1.867,-13.335) 47(-1.867,-14.605) 48(1.867,-14.605)
  silkscreen extent -2.29,-15.24 1.71,15.62, body extent -2.92,-15.24 2.92,15.24, height 4.33
SER1360 [mm] "SER1360"
  rect 2.26x3.07 smd: 1(-5.26,3.605) 2(-5.26,-3.605)
  rect 2.26x2.77 smd: 3(5.26,0)
  silkscreen extent -7,-6.5 7,6.5, body extent -6.5,-6.45 6.5,6.45, height 5.8
SM_RADIAL_H13 [mm] "12.5 x 13.5mm:  Panasonic H13"
  rect 5.7x2 smd: 1(-4.85,0) 2(4.85,0)
  silkscreen extent -6.85,-6.85 6.85,6.85, body extent -6.85,-6.85 6.85,6.85, height 14
SMA [mm] "Molded Diode, 2-Leads, Body 4.3x2.6mm, IPC Medium Density, based on OnSemi component dimensions and land pattern"
  rect 2x2 smd: 1(-2,0) 2(2,0)
  silkscreen extent -3.66,-1.57 2.79,1.57, body extent -2.6,-1.3 2.6,1.3, height 2.42
SML-P1_YELLOW-GREEN [mm] "Rohm Semiconductor"
  rect 0.5x0.6 smd: 1(-0.45,0) 2(0.45,0)
  silkscreen extent -0.63,-0.61 1.33,0.61, body extent -0.55,-0.35 0.55,0.35, height 0.25
SNT-100-BK-G [mil] "Samtec STEP model"
  round 1 on Mech3: 0(0,0)
  body extent -100,-50 100,50, height 344
SOT-23 [mm] "SOT23, 3-Leads, Body 2.9x1.3mm, Pitch 0.95mm, Lead Span 2.5mm, IPC Medium Density"
  rect 1.5x0.6 smd: 1(-0.95,0.95) 2(-0.95,-0.95) 3(0.95,0)
  silkscreen extent 0.2,-1.5 0.7,1.5, body extent -1.16,-1.45 1.21,1.45, height 1
SW_SKRKAEE010 [mm] "Alps recommended land pattern"
  rect 0.8x2 smd: 1(-2.1,0) 2(2.1,0)
  body extent -2.4,-1.45 2.4,1.45, height 1.96
TI_Stacked_SolderMask_Small [mil]
  rect 900x250 smd paste-125 mask-125: 0(0,0)
TSW-102-07-G-S [mm] "Samtec 100mil, 1x2, 230 mil above insulator"
  rect 1.65x1.65 hole 1.016 mask+0: 1(-1.27,0)
  round 1.65 hole 1.016 mask+0: 2(1.27,0)
  silkscreen extent -3.56,-1.27 2.54,1.27, body extent -2.54,-1.27 2.54,1.27, height 8.38
TSW-105-07-G-S [mm] "Samtec 100mil, 1x5, 230 mil above insulator"
  rect 1.65x1.65 hole 1.016 mask+0: 1(-5.08,0)
  round 1.65 hole 1.016 mask+0: 2(-2.54,0) 3(0,0) 4(2.54,0) 5(5.08,0)
  silkscreen extent -7.37,-1.27 6.35,1.27, body extent -6.35,-1.27 6.35,1.27, height 8.38
VLCF5028 [mm] "TDK"
  rect 2.1x3 smd: 1(-1.7,0) 2(1.7,0)
  Top Layer region: 0.65,2.45 1.85,2.45 2.75,1.55 2.75,1.4 0.65,1.4
  Top Layer region: 0.65,-2.45 1.85,-2.45 2.75,-1.55 2.75,-1.4 0.65,-1.4
  Top Layer region: -0.65,-2.45 -1.85,-2.45 -2.75,-1.55 -2.75,-1.4 -0.65,-1.4
  Top Layer region: -0.65,2.45 -1.85,2.45 -2.75,1.55 -2.75,1.4 -0.65,1.4
  body extent -2.6,-2.6 2.6,2.6, height 2.8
